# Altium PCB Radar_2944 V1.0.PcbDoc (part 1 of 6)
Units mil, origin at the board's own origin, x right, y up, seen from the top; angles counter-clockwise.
Board outline 3544.83 x 2556.65 mil, 8 copper layers (Top Layer, GND1, SIG1, PWR1, PWR2, SIG2, GND2, Bottom Layer), stack 55.2 mil thick; 301 components, 253 nets, 1055 pads, 1340 vias.
Unrouted connection lines stored in the file: 12.
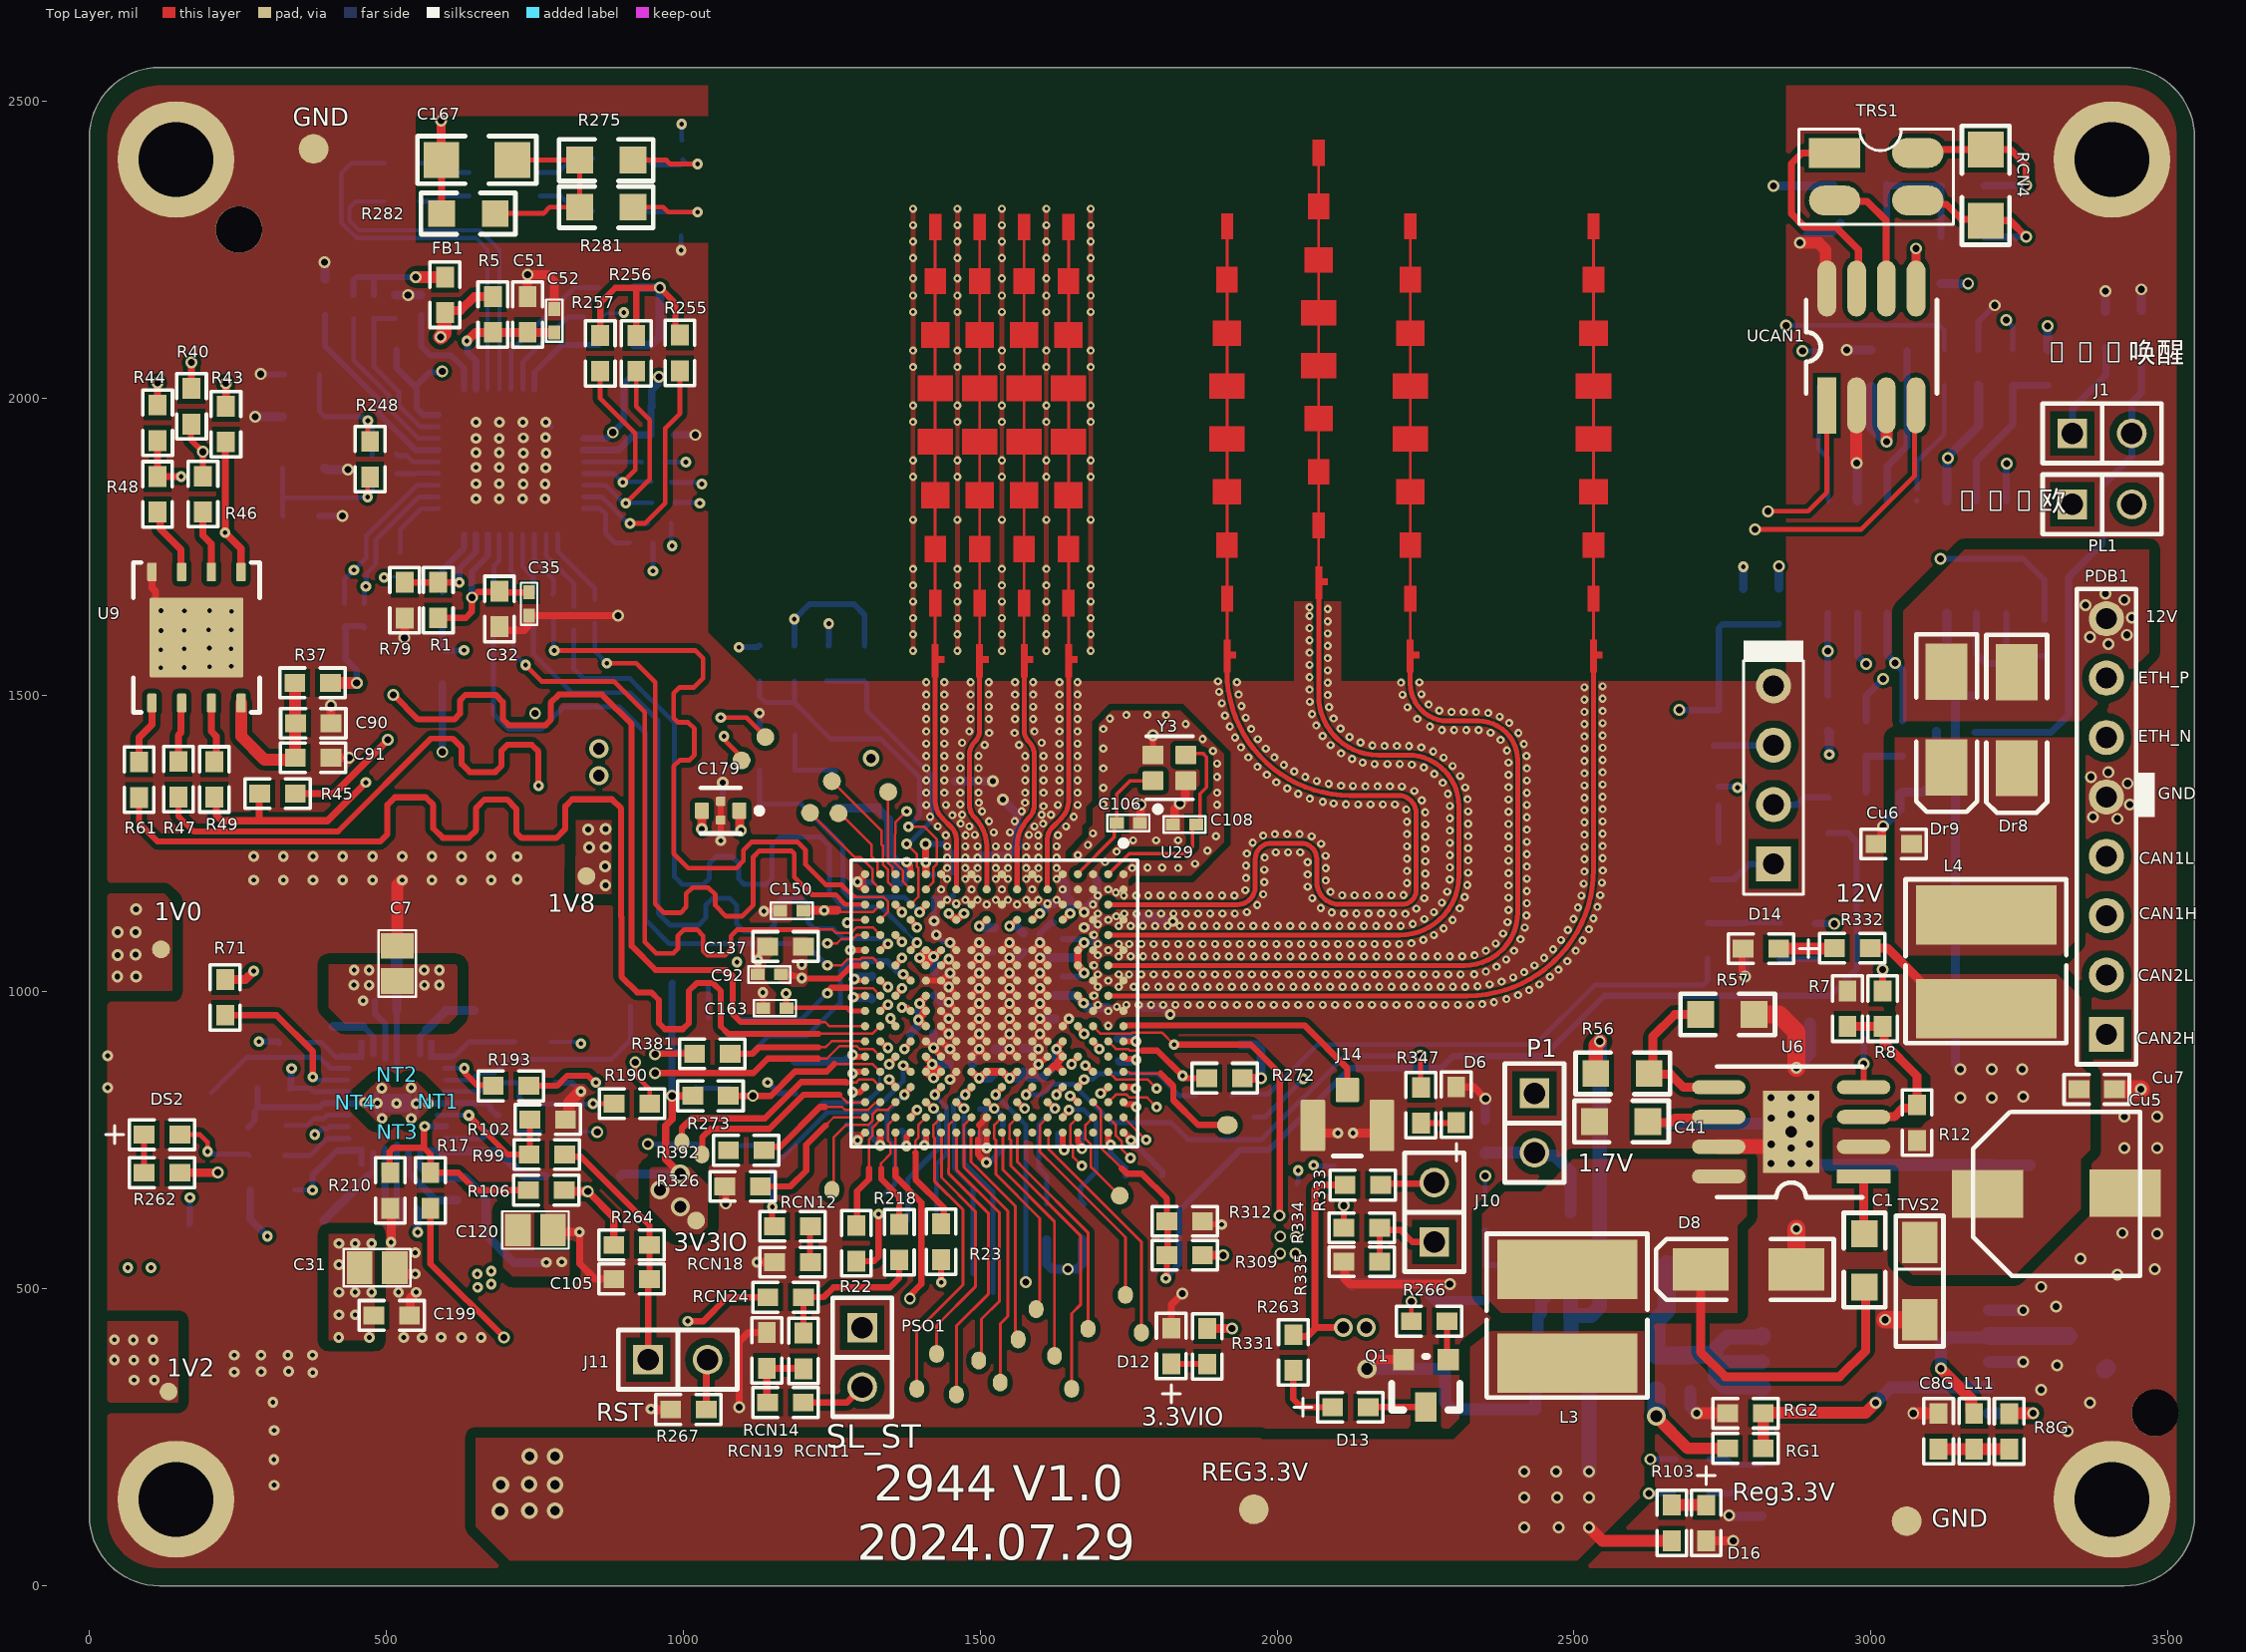
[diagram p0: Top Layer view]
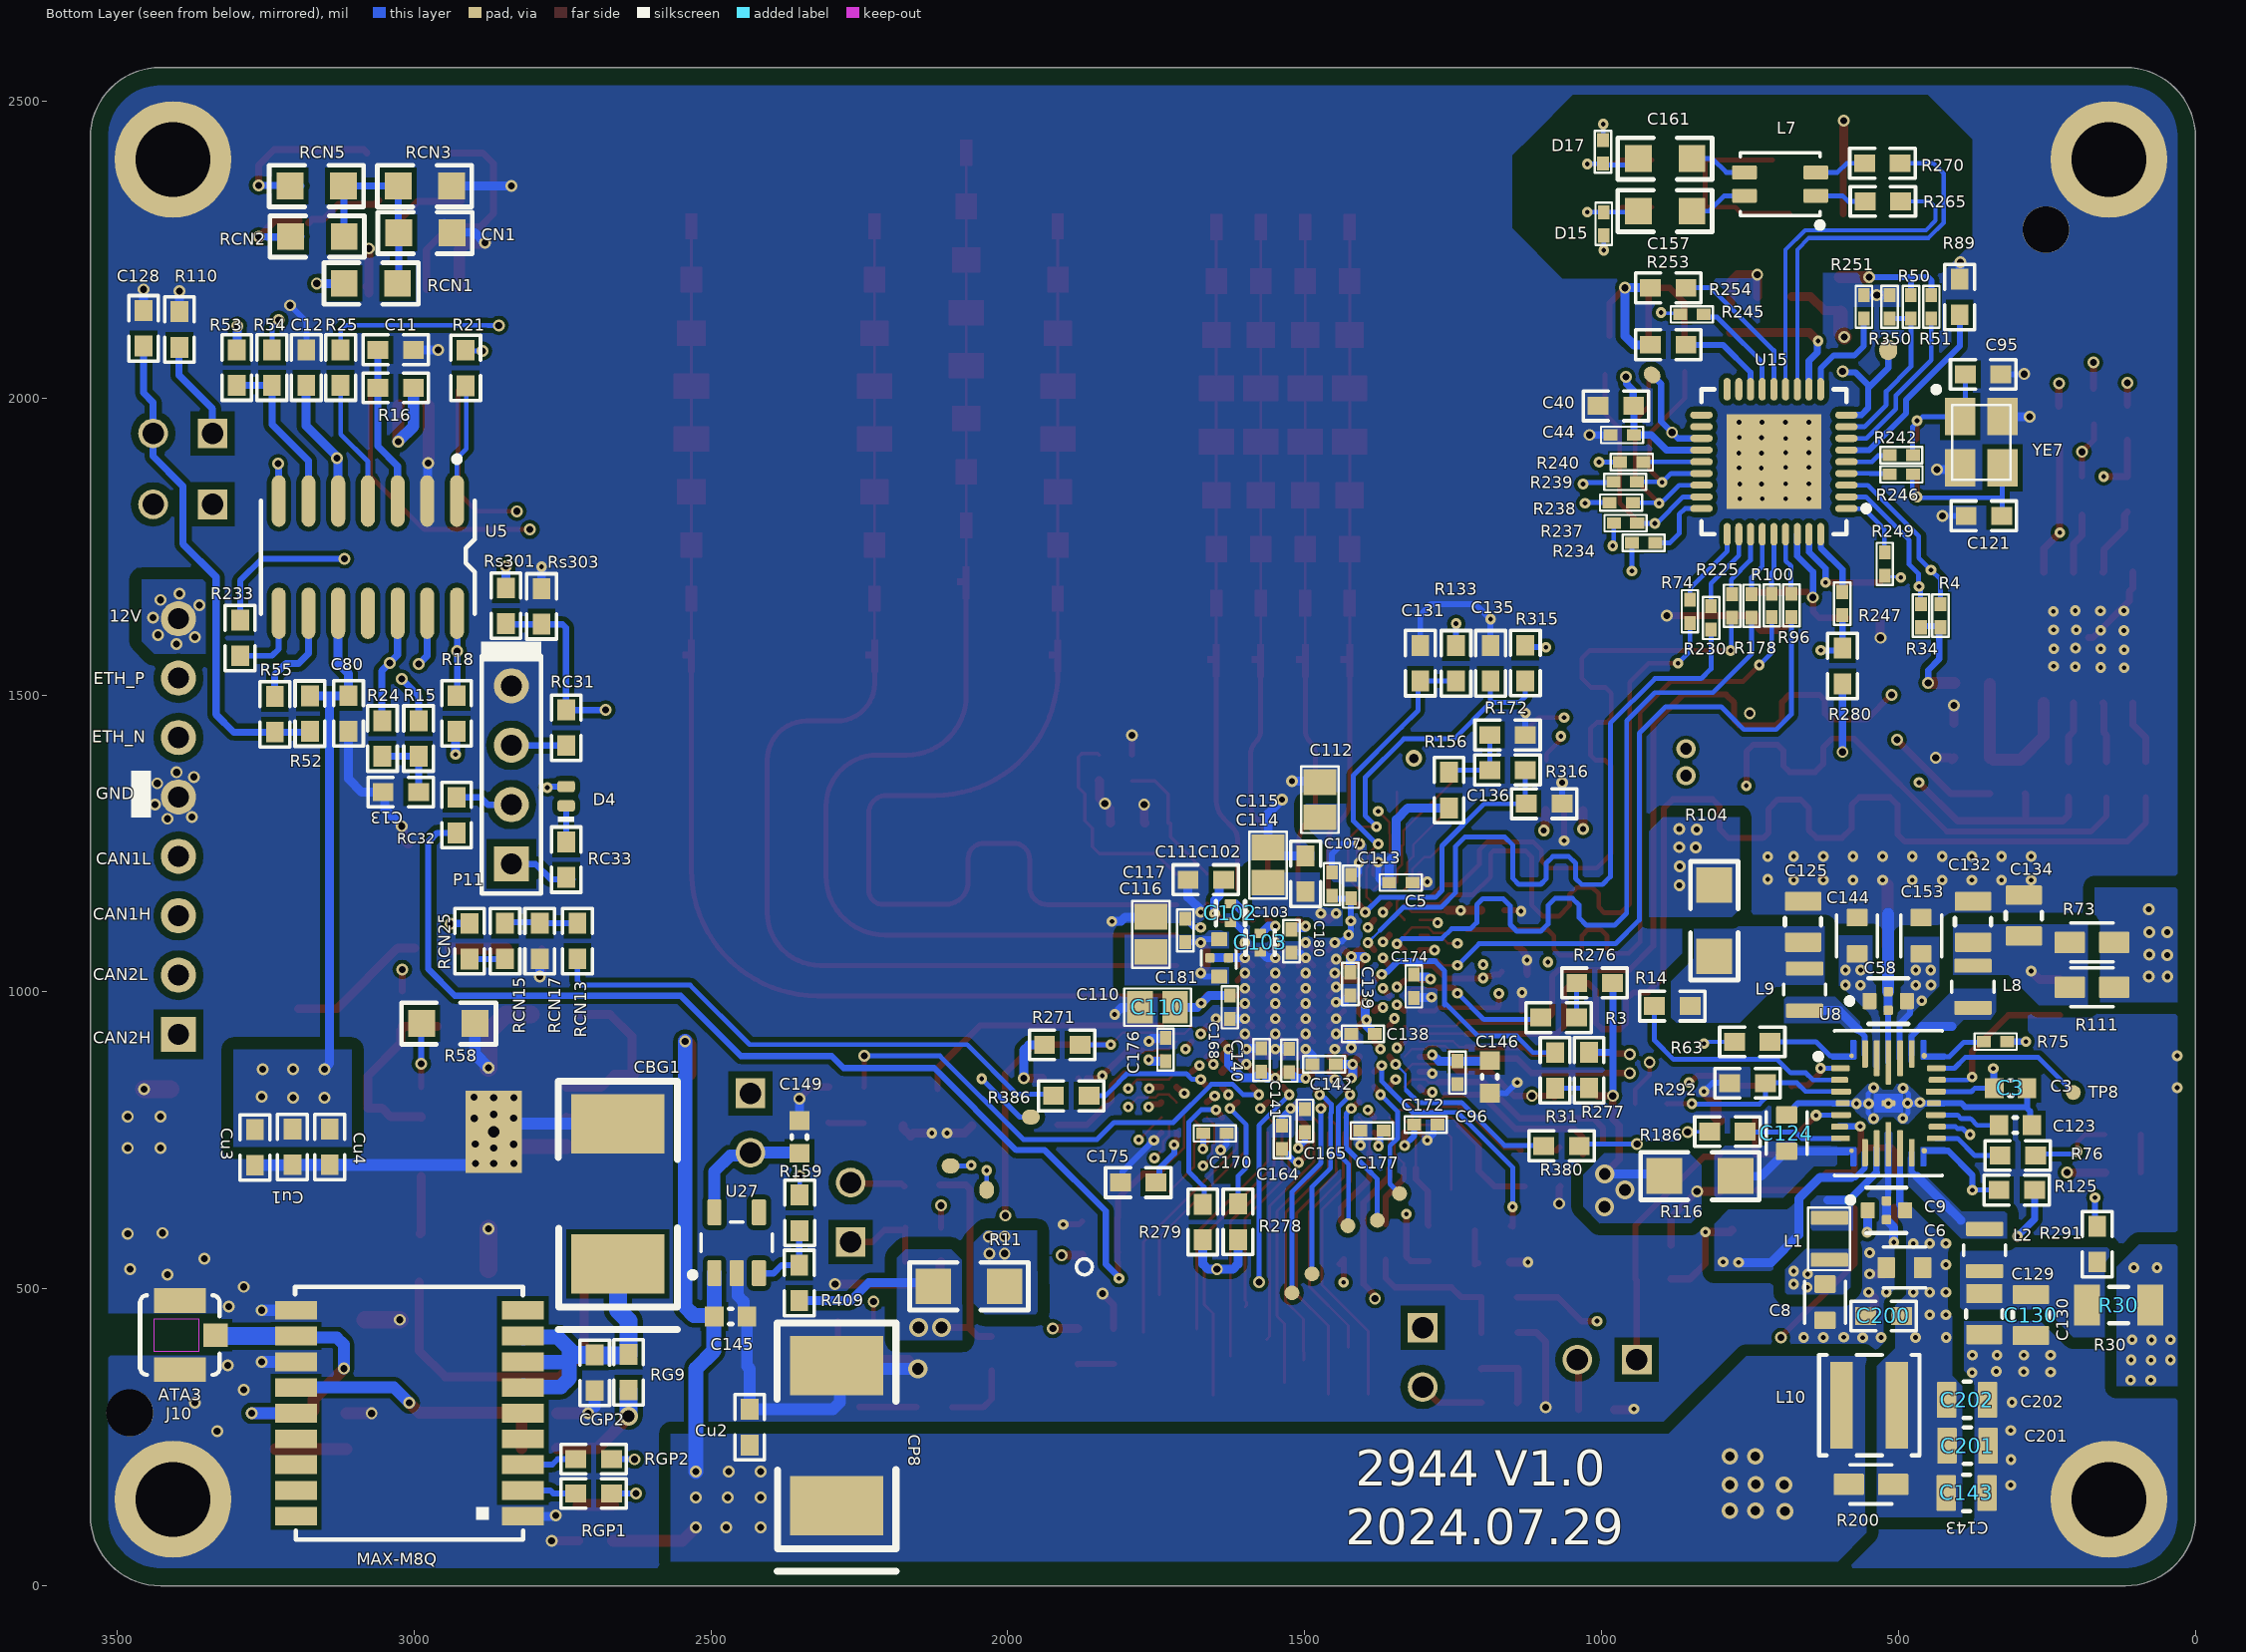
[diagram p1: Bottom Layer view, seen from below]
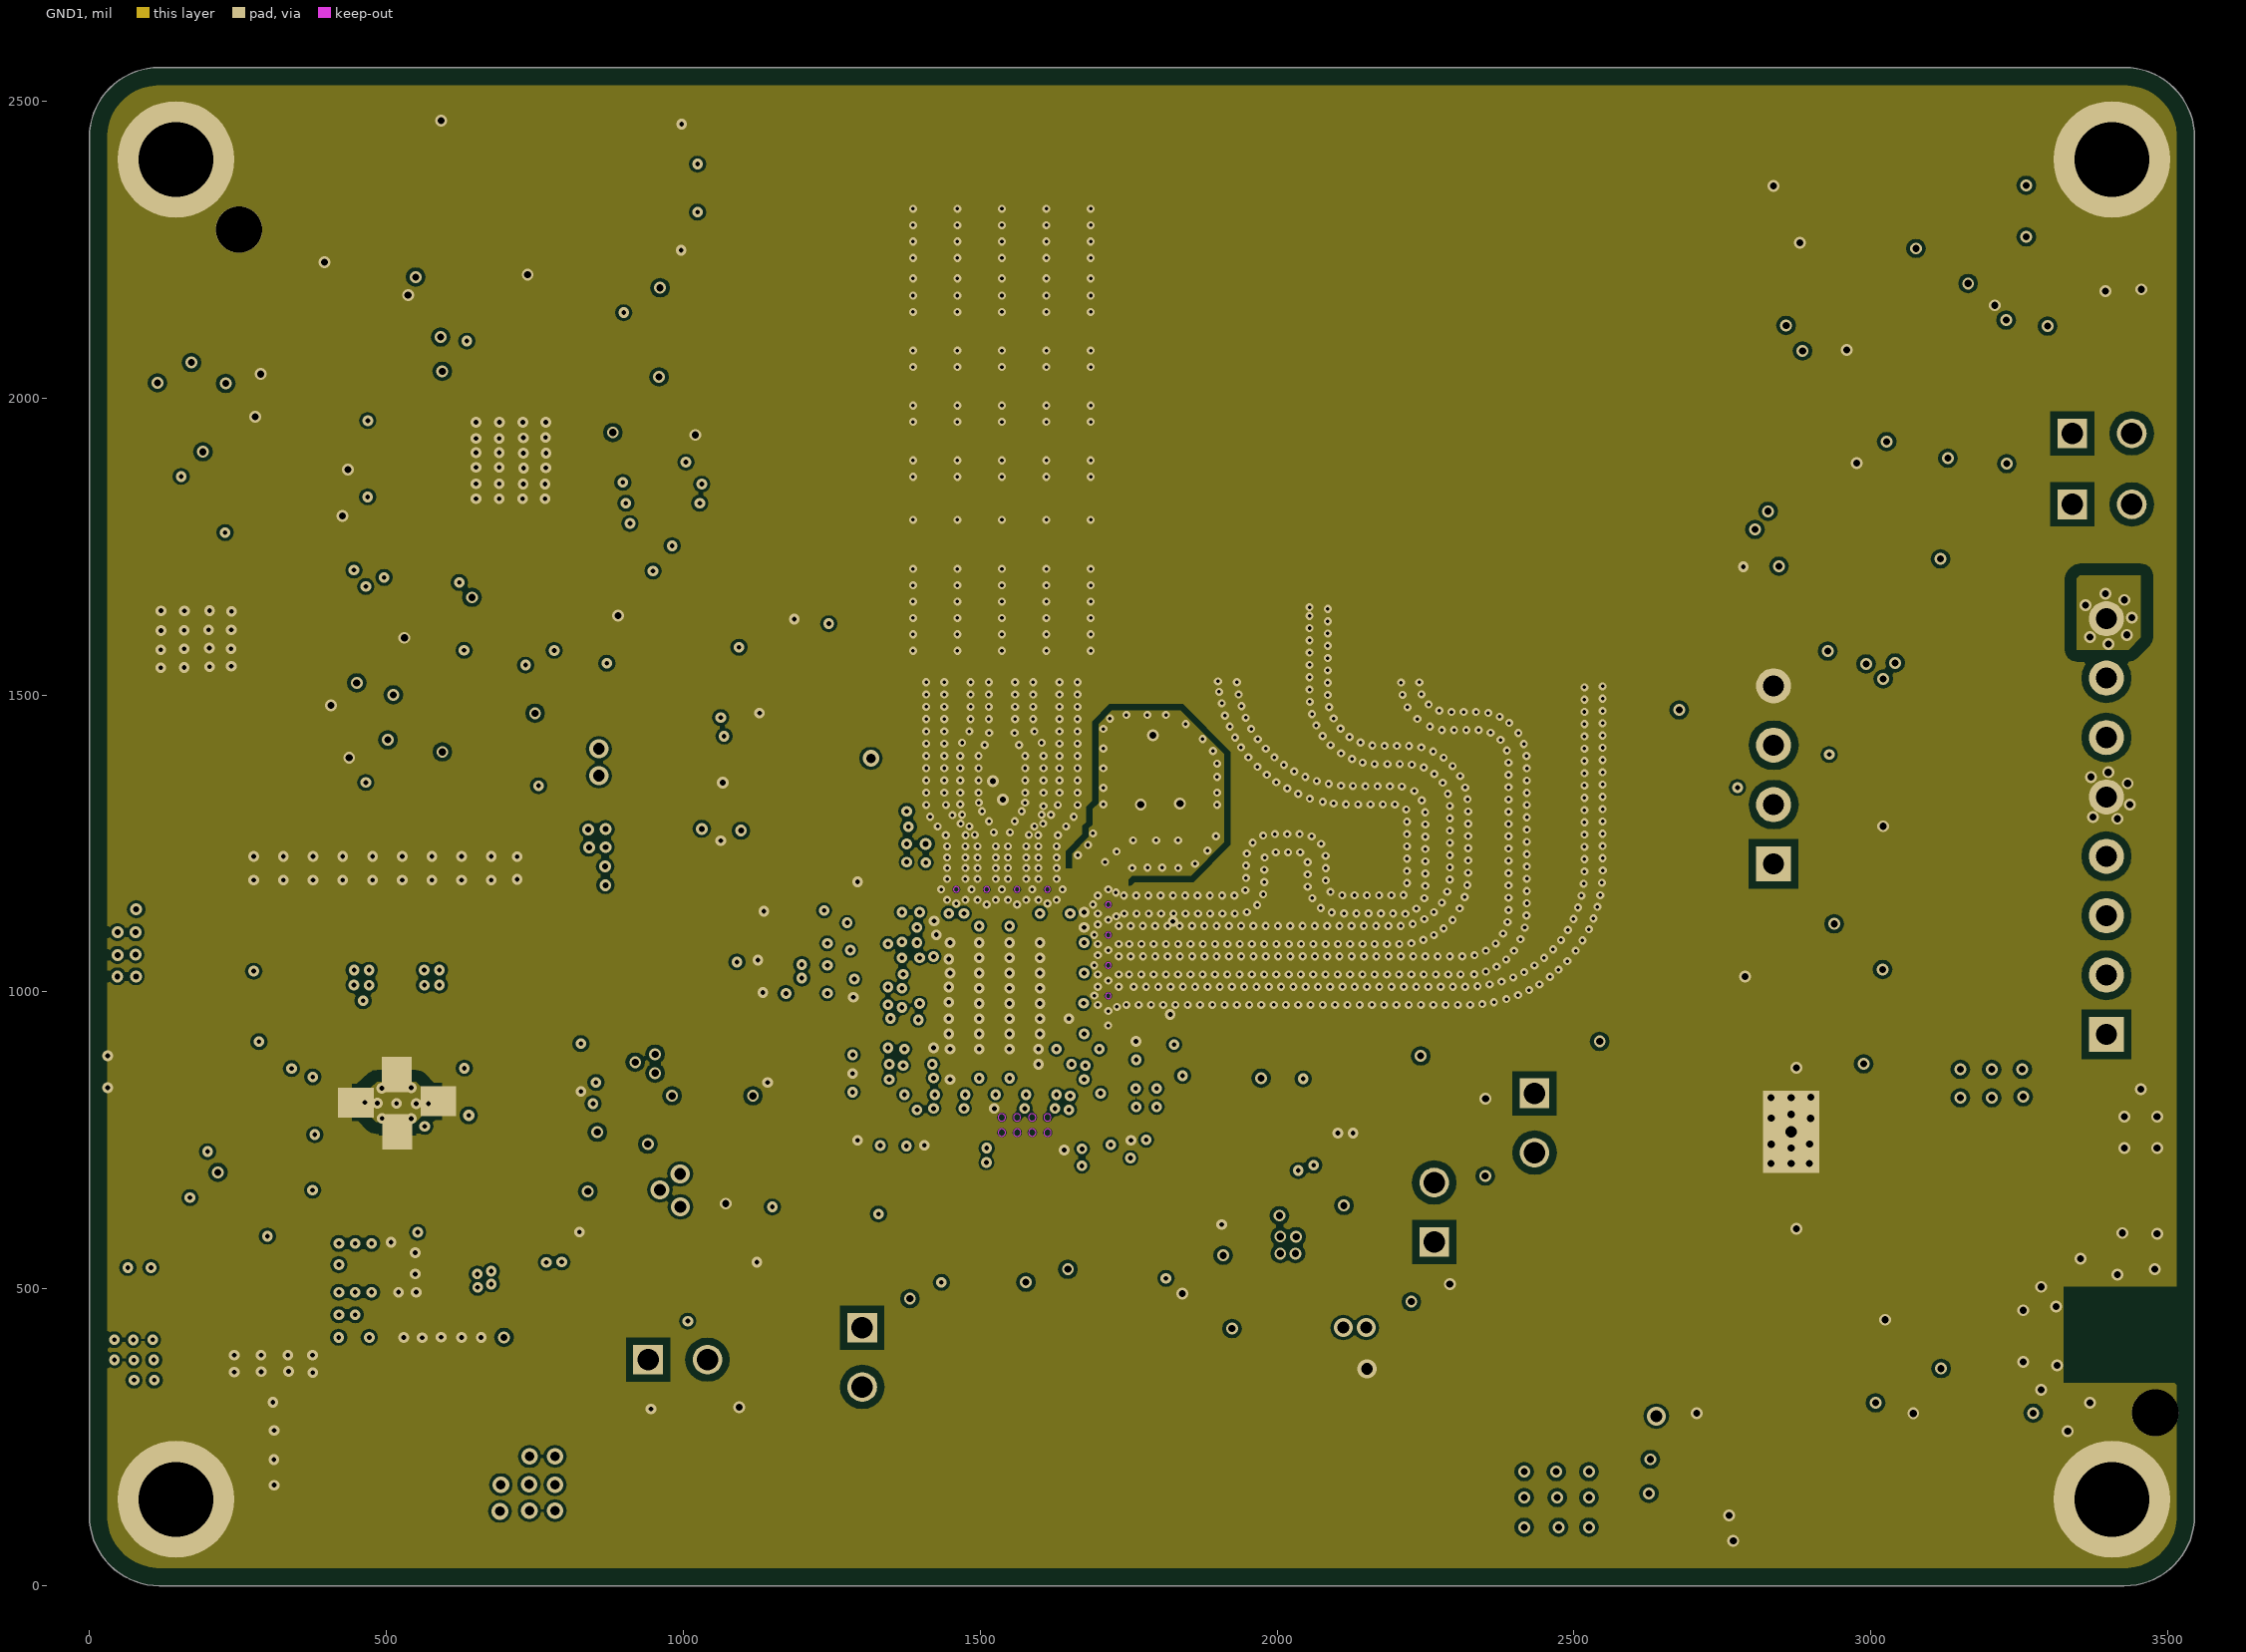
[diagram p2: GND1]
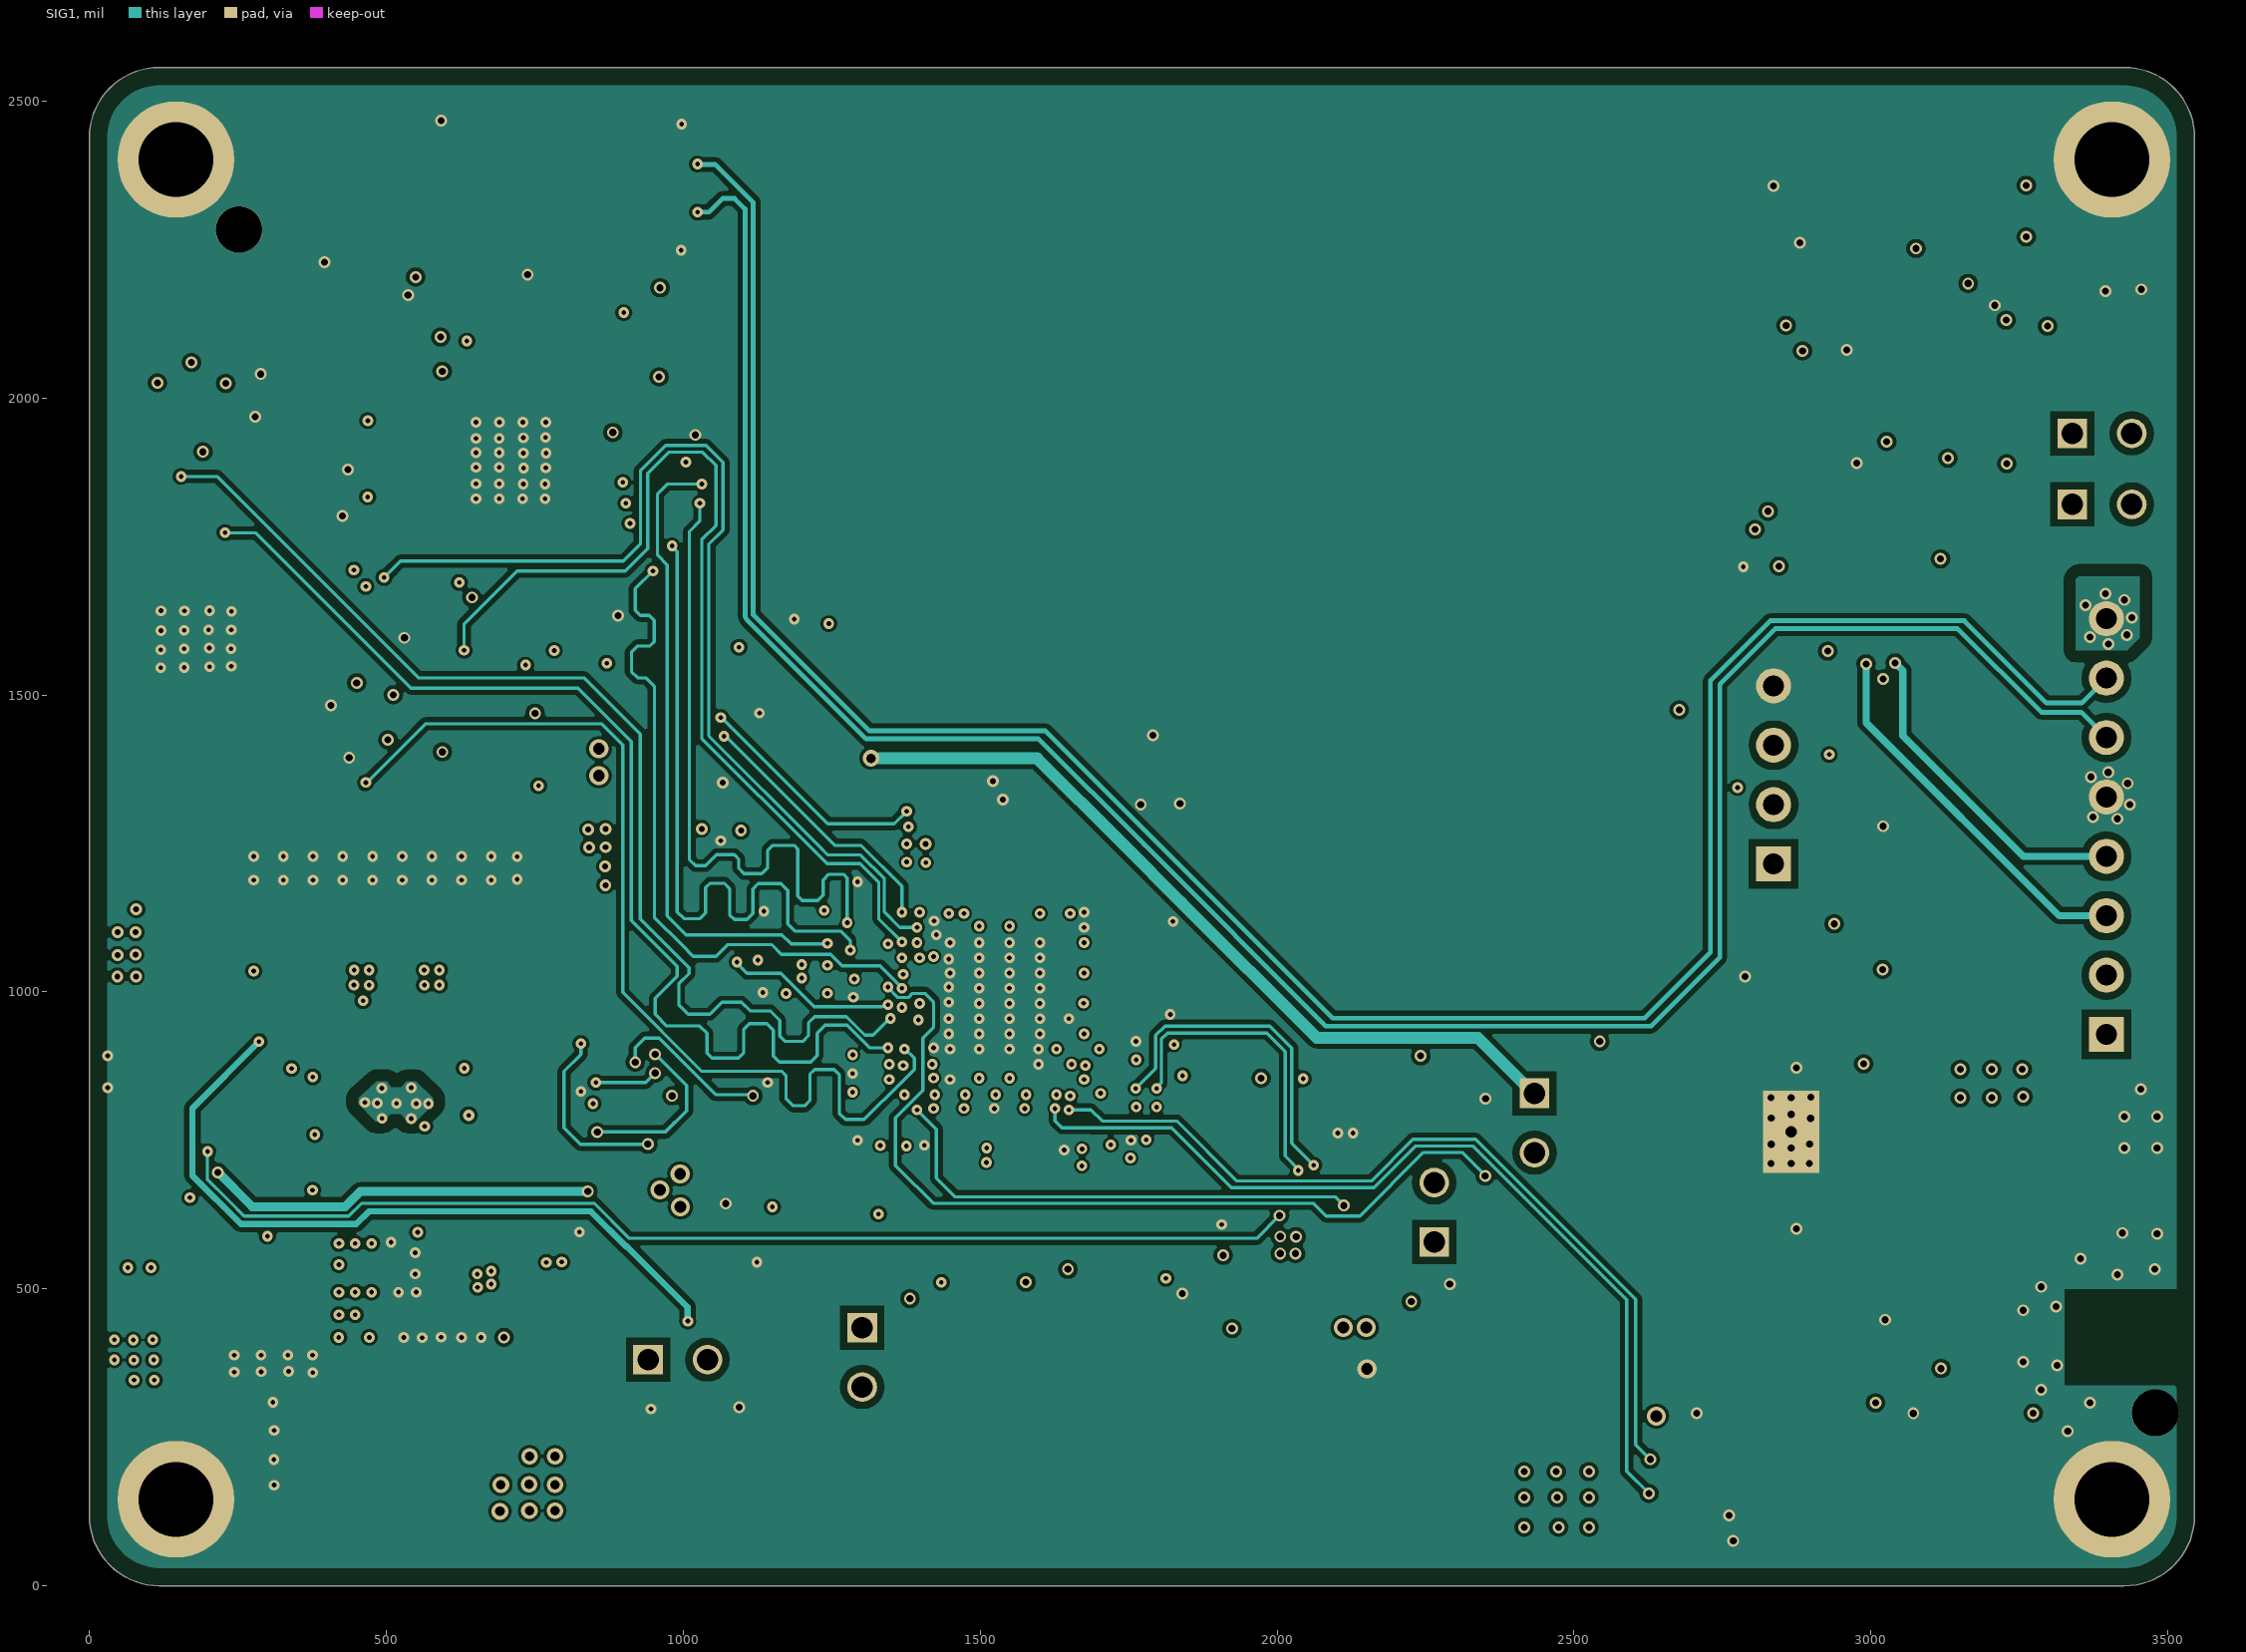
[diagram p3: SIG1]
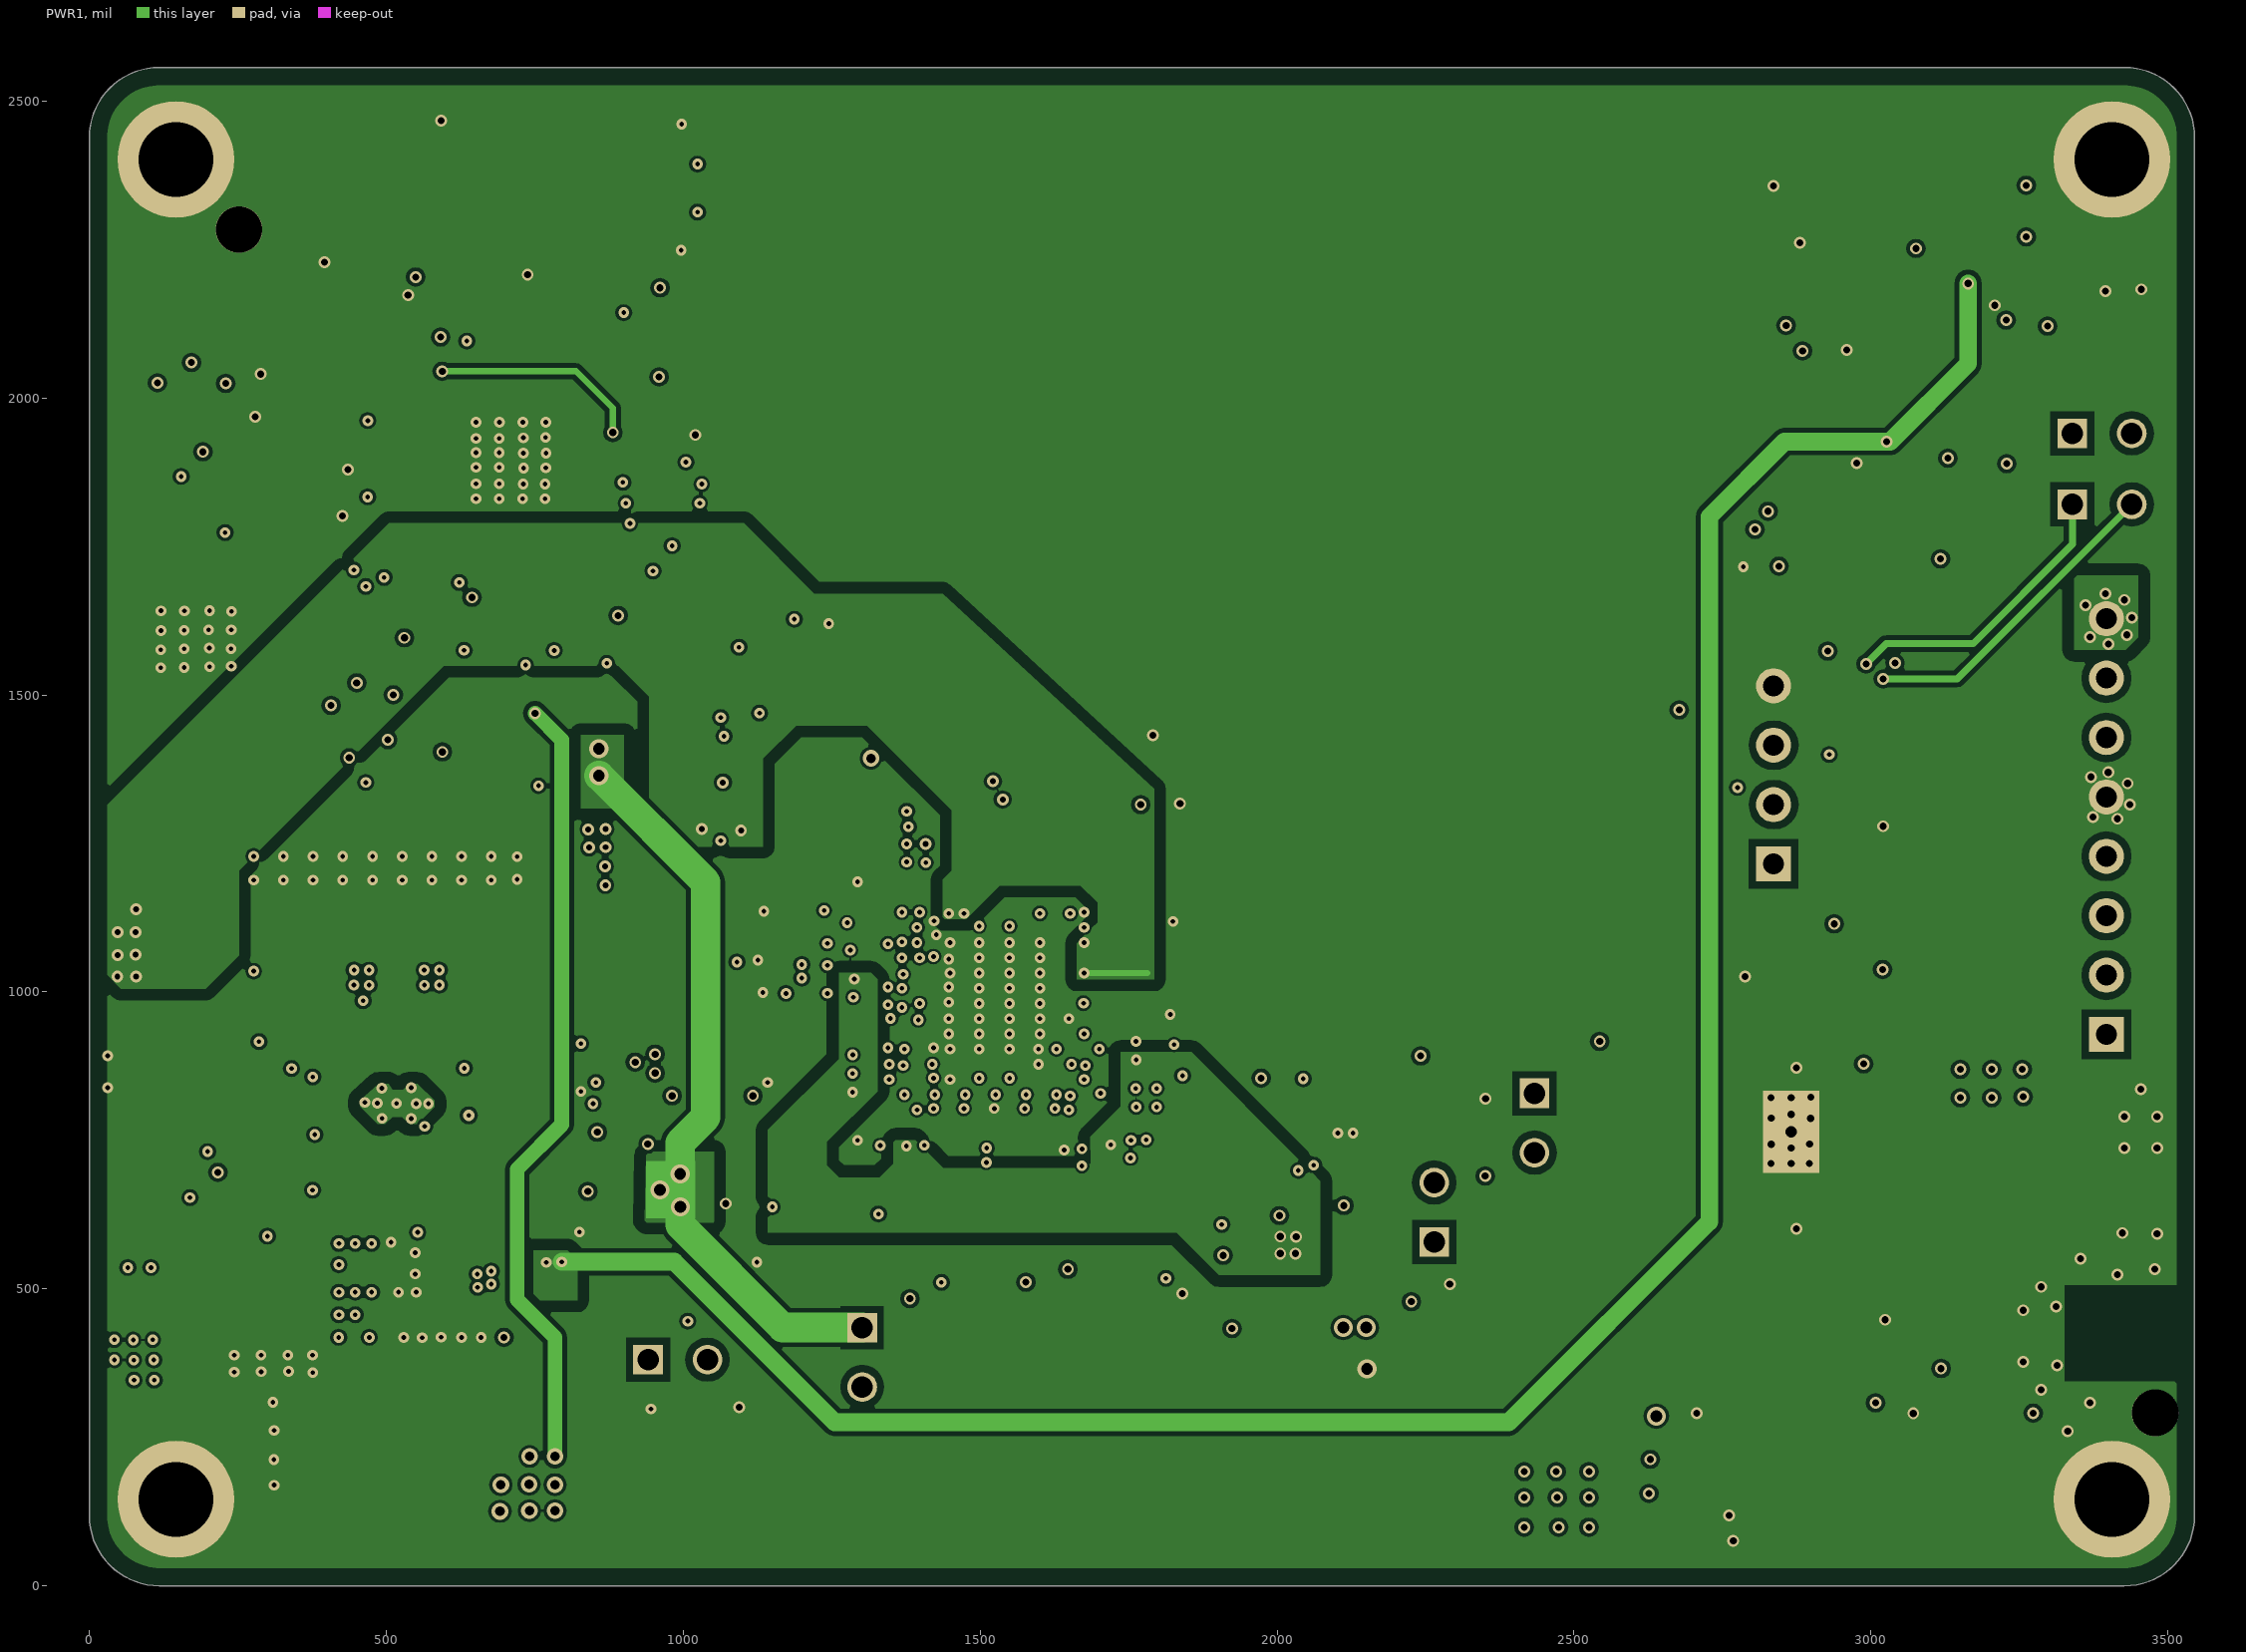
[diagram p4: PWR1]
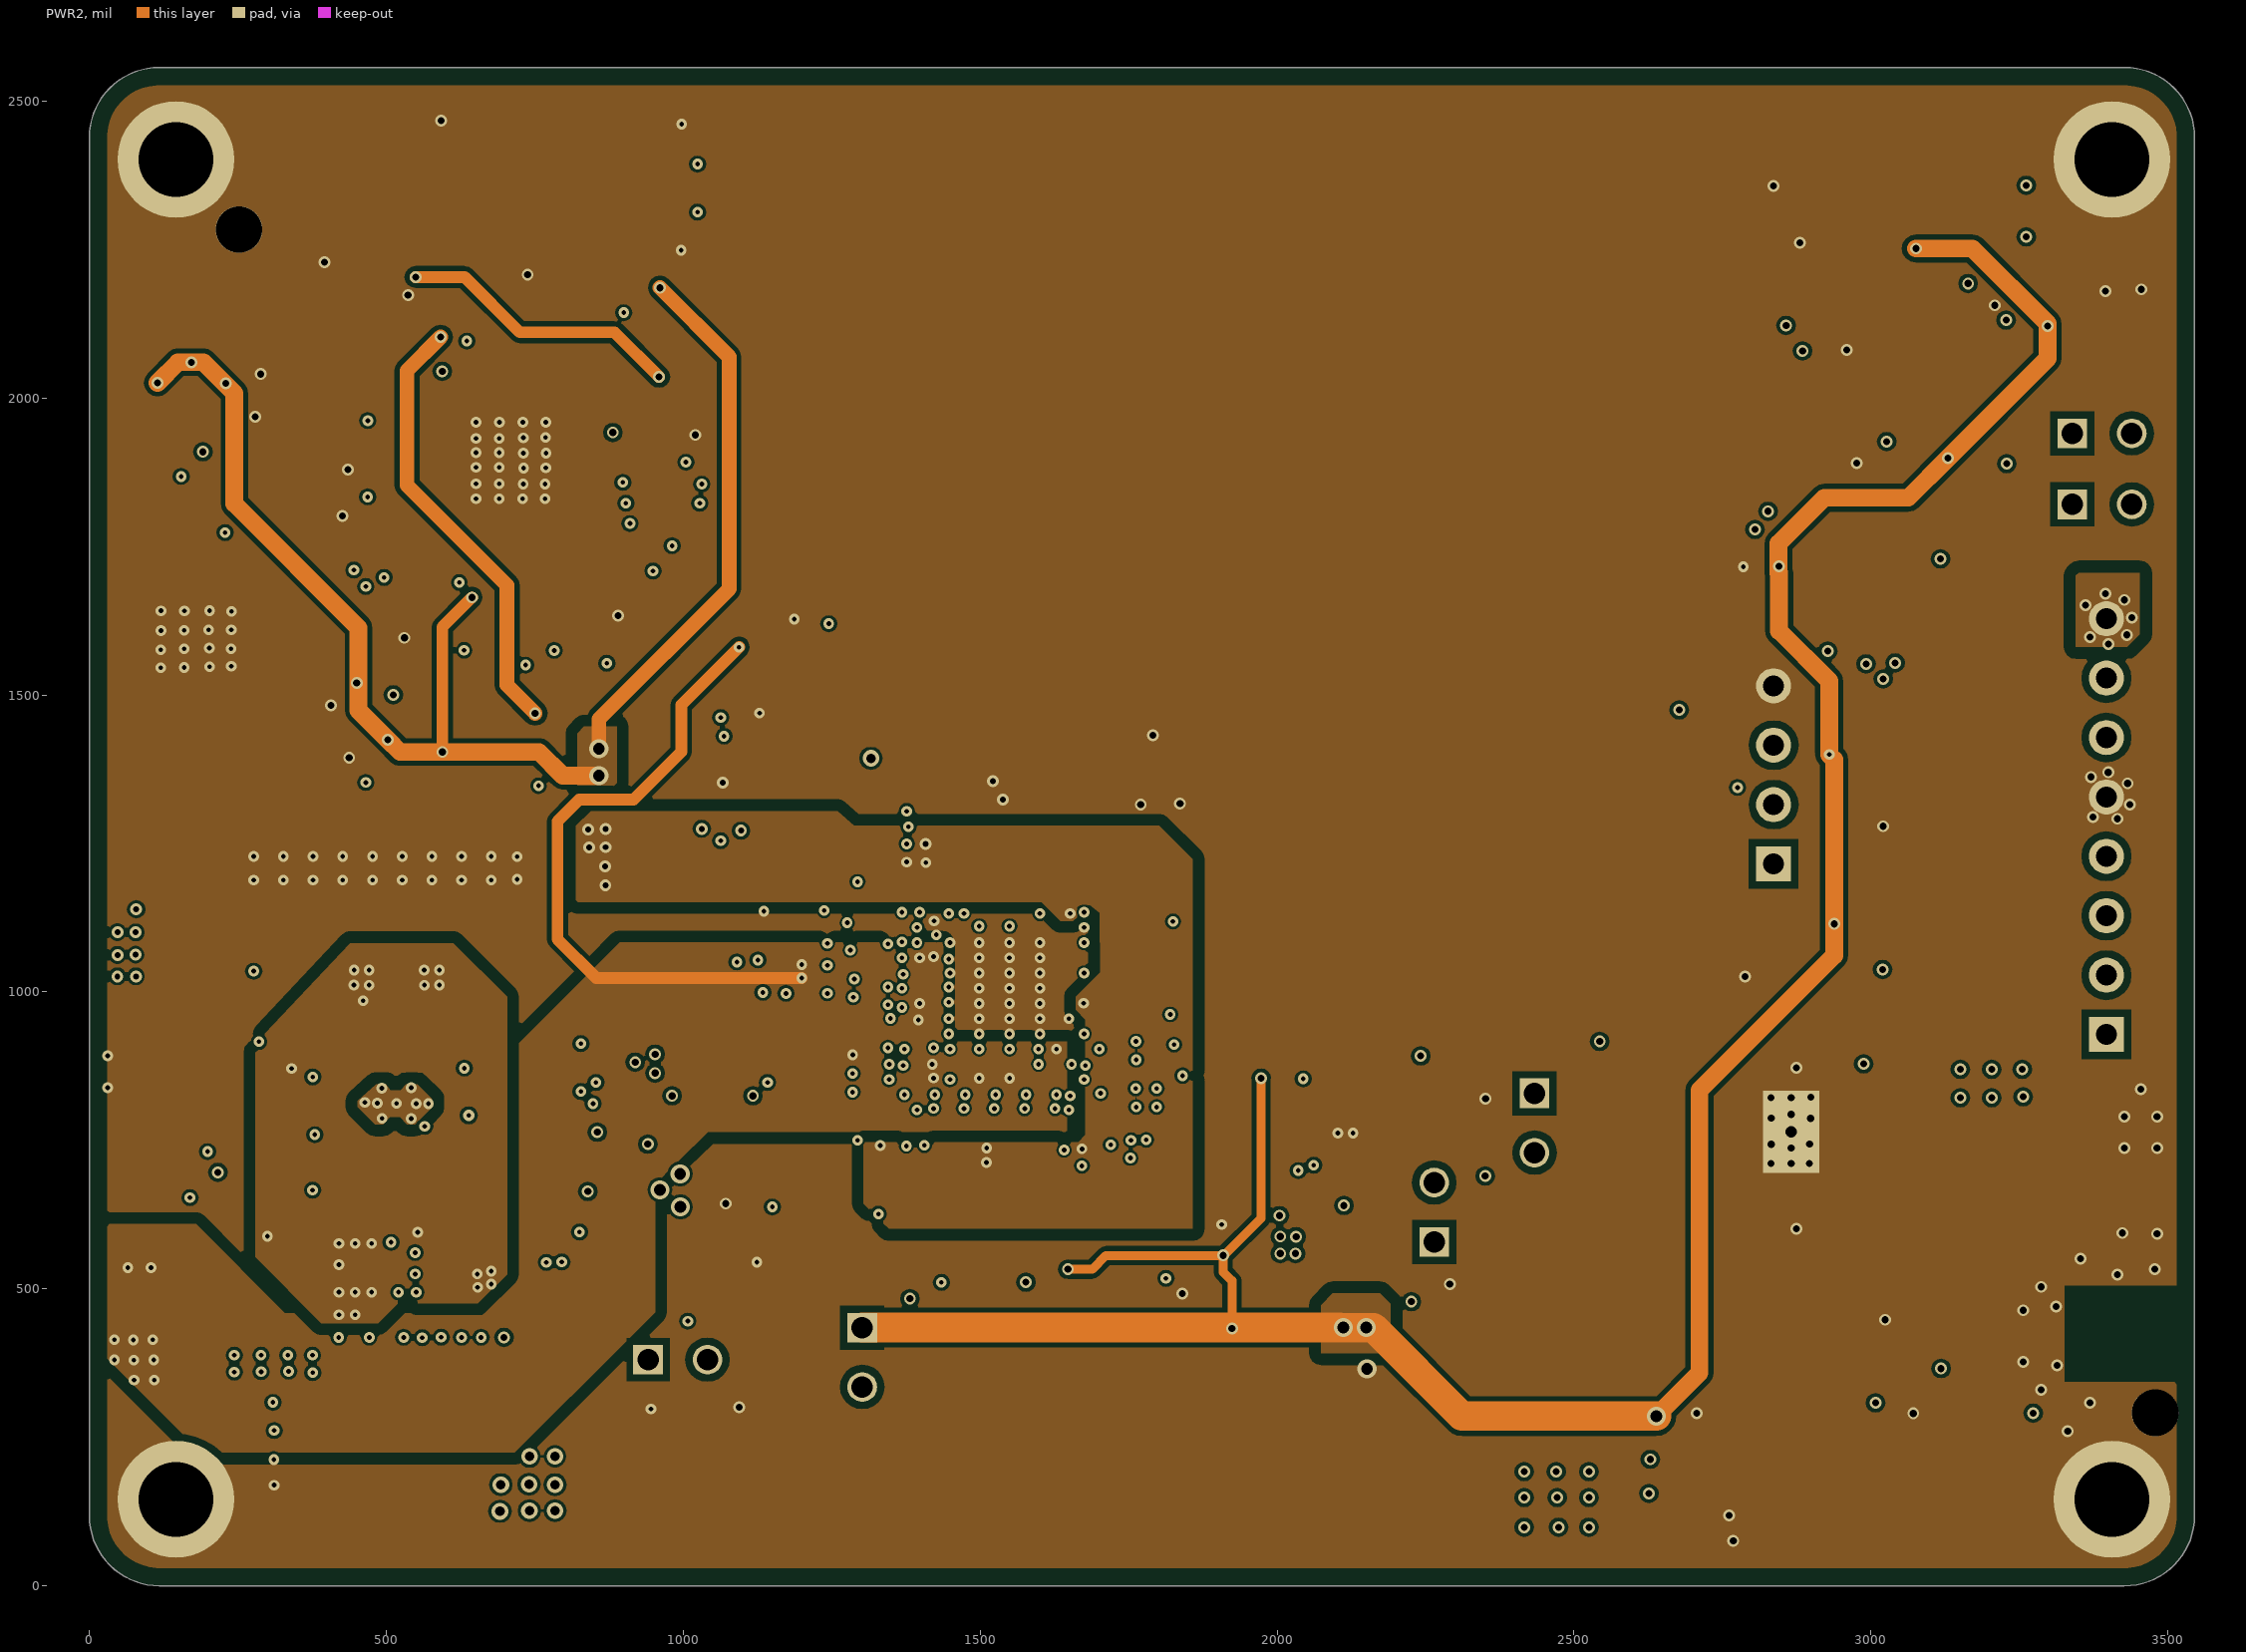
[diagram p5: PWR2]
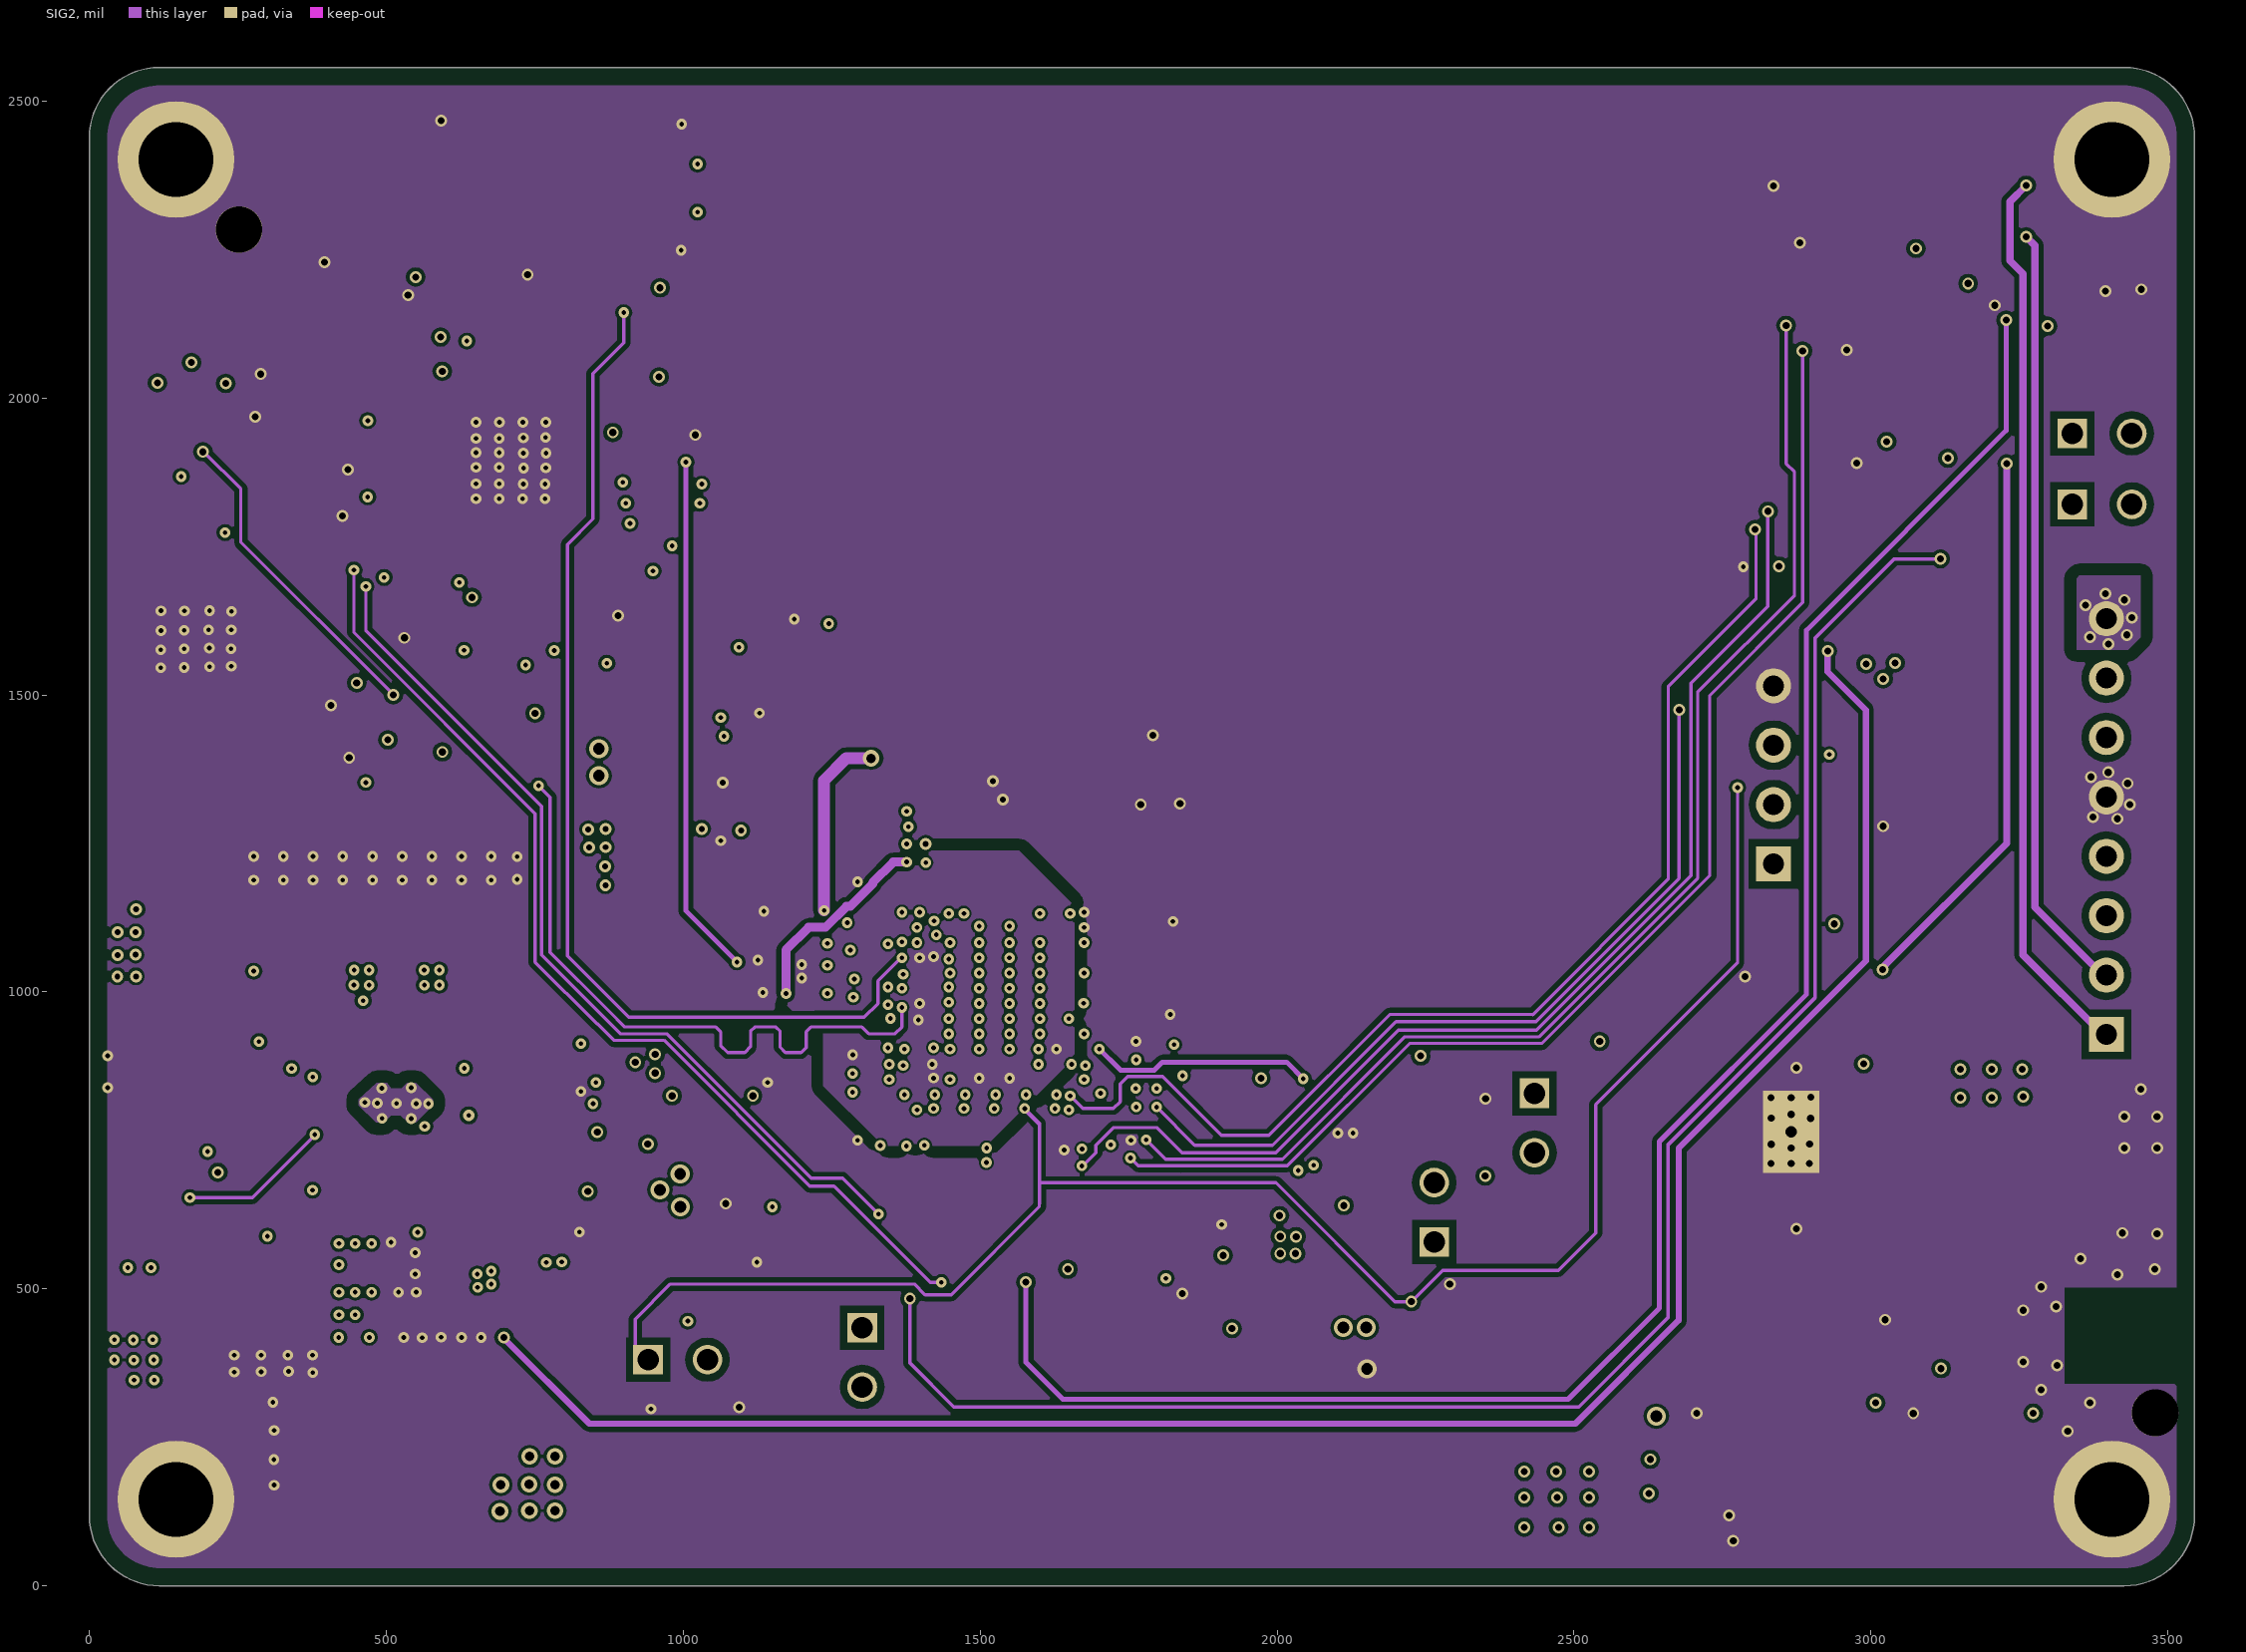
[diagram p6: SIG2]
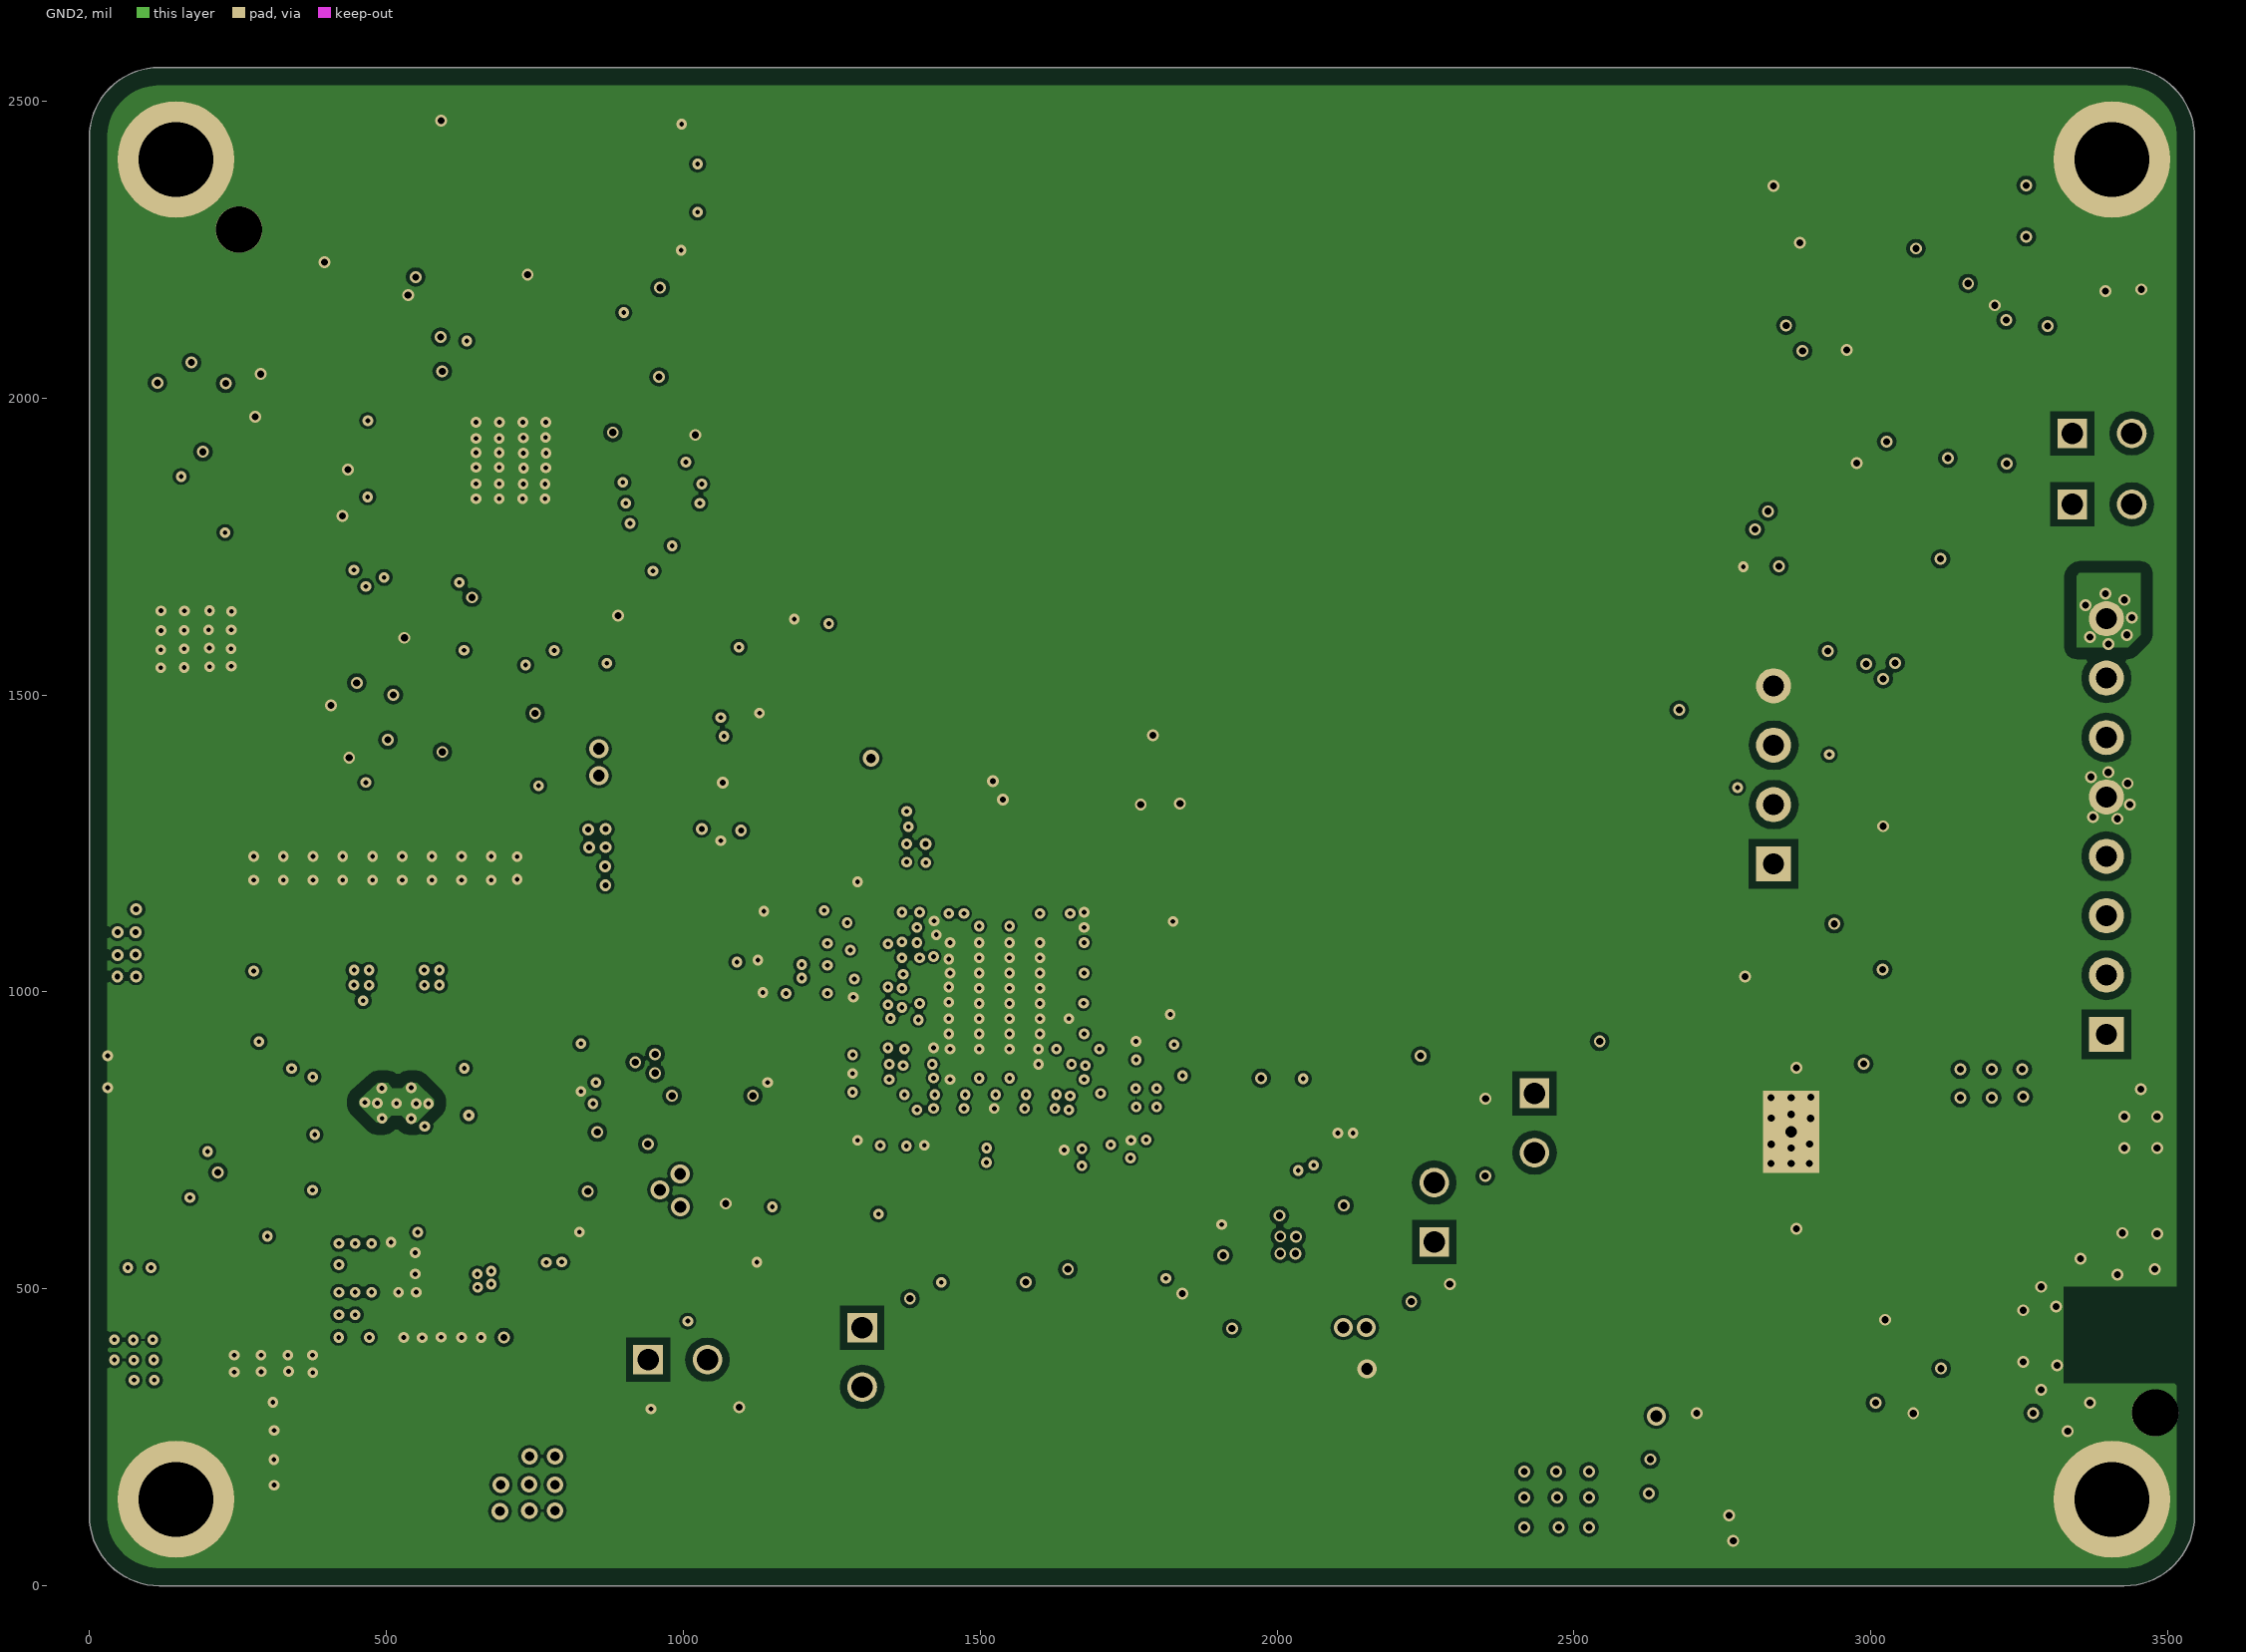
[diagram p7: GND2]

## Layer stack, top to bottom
Top Solder: solder mask 0.8, Solder Resist, Dk 3.5
Top Layer: signal copper 1.6
Dielectric 1: prepreg 5, RO3003, Dk 3
GND1: signal copper 1.4
Dielectric 2: core 5, FR-4 High Tg, Dk 4.04
SIG1: signal copper 0.7
Dielectric 3: prepreg 10, FR-4 High Tg, Dk 4.04
PWR1: signal copper 1.4
Dielectric 4: prepreg 5, FR-4 High Tg, Dk 4.04
PWR2: signal copper 1.4
Dielectric 5: prepreg 10, FR-4 High Tg, Dk 4.04
SIG2: signal copper 0.7
Dielectric 6: core 5, FR-4 High Tg, Dk 4.04
GND2: signal copper 1.4
Dielectric 7: prepreg 5, FR-4 High Tg, Dk 4.04
Bottom Layer: signal copper 1.6
Bottom Solder: solder mask 0.8, Solder Resist, Dk 3.5

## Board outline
0.01,118.17 0.01,2438.42 -0.02,2438.42 cw(c118.09,2438.42) 118.09,2556.53 3426.69,2556.53 cw(c3426.69,2438.42) 3544.81,2438.42 3544.78,2438.42 3544.78,117.99 3544.6,117.99 cw(c3426.49,117.99) 3426.49,-0.12 3426.49,0.01 118.17,0.01 118.17,0.06 cw(c118.17,118.17)

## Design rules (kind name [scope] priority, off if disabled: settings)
AcuteAngle [All] p1: minimum=4.50000000000000E+0001 checktracksonly=TRUE
AssemblyTestPointUsage [All] p1: valid=2
BoardOutlineClearance BoardOutlineClearance_MountingHoles [OnCopper and InComponentClass('Mounting Holes')] p1: gap=39.37 ignorepadtopadclearanceinfootprint=FALSE
BoardOutlineClearance BoardOutlineClearance_Poly [OnCopper and IsPoly] p2: gap=30 ignorepadtopadclearanceinfootprint=FALSE
BoardOutlineClearance [OnCopper and Not InComponentClass('Logo') and not InComponentClass('FiducialMark')and not InComponentClass('RA PARTS') and not InPoly] p3: gap=80 ignorepadtopadclearanceinfootprint=FALSE except(0: THPad-OutlineEdge Text-OutlineEdge Text-CavityEdge Text-CutoutEdge Text-SplitBarrior Text-SplitContinuation; 19: Fill-OutlineEdge; 30: Arc-OutlineEdge Track-OutlineEdge SMDPad-OutlineEdge Via-OutlineEdge Poly-OutlineEdge Region-OutlineEdge)
Clearance Clearance_2 [InComponent('PDB1')] p1: gap=8 ignorepadtopadclearanceinfootprint=TRUE except(0: SMDPad-Via THPad-Via Via-Via; 1: Arc-Text Track-Text SMDPad-Text THPad-Text Via-Text Fill-Text Poly-Text Region-Text Text-Text; 5.5: Arc-Arc Arc-Track Track-Track; 6: Via-Fill Via-Poly Via-Region; 7: Arc-Via Track-Via; 7.7: Arc-SMDPad Track-SMDPad; 9: Arc-Hole Track-Hole; 10: Via-Hole Fill-Hole Poly-Hole Region-Hole; 12: SMDPad-THPad SMDPad-Hole THPad-THPad THPad-Fill THPad-Poly THPad-Region THPad-Hole; 18: Fill-Fill Fill-Poly Fill-Region Poly-Poly Poly-Region Region-Region)
Clearance Clearance_1 [InNamedPolygon('Top Layer-AGND 1')] p2: gap=10 ignorepadtopadclearanceinfootprint=FALSE except(0: Arc-Hole Track-Hole SMDPad-Via SMDPad-Hole THPad-Hole Via-Hole Fill-Hole Poly-Hole Region-Hole Text-Hole)
Clearance Clearance_Keepouts [IsKeepOut] p3: gap=1 ignorepadtopadclearanceinfootprint=FALSE except(0: Arc-Via Track-Via SMDPad-Via)
Clearance RF_Via [InNetClass('Antenna')] p4: gap=10 ignorepadtopadclearanceinfootprint=TRUE except(0: Track-Region SMDPad-Via SMDPad-Region THPad-Region Via-Region; 3.78: Track-Poly; 3.94: Arc-Poly; 4: Arc-Via Arc-Hole Track-Via Track-Hole; 4.69: Poly-Region; 6: Region-Hole; 9.45: SMDPad-Poly)
Clearance Clearance_Poly_INT [InPolygon vs (OnLayer('GND1') OR OnLayer('SIG1') OR  OnLayer('GND2') OR OnLayer('PWR1') OR OnLayer('PWR2') OR OnLayer('GND3') OR OnLayer('SIG2') OR OnLayer('GND4'))] p5: gap=8 ignorepadtopadclearanceinfootprint=TRUE except(0: SMDPad-Via; 5: Arc-Text Track-Text SMDPad-Text THPad-Text Via-Text Fill-Text Poly-Text Region-Text Text-Text; 6: Arc-Via Track-Via SMDPad-Fill SMDPad-Poly SMDPad-Region; 10: Arc-THPad Arc-Hole Track-THPad Track-Hole Via-Fill Via-Poly Via-Region Via-Hole Fill-Hole Poly-Hole Region-Hole; 12: SMDPad-SMDPad SMDPad-THPad SMDPad-Hole THPad-THPad THPad-Hole Via-Via; 20: Fill-Fill Fill-Poly Fill-Region Poly-Poly Poly-Region Region-Region)
Clearance Clearance_FiducialMark [IsKeepOut and InComponentClass('FiducialMark') vs IsPad and InComponentClass('FiducialMark')] p6: gap=0 ignorepadtopadclearanceinfootprint=FALSE
Clearance 0.65MM_BGA [WithinRoom('BGA')] p7: gap=1 ignorepadtopadclearanceinfootprint=TRUE except(0: Arc-Region Track-Region SMDPad-Via SMDPad-Region THPad-Region Via-Region; 3.81: Arc-SMDPad Track-SMDPad; 3.9: Arc-Arc Arc-Track Track-Track; 4: Arc-Via Arc-Fill Arc-Poly Track-Via Track-Fill Via-Fill Via-Poly; 5: Via-Via; 7: Via-Hole; 8: Arc-Hole Track-Poly Track-Hole SMDPad-SMDPad SMDPad-Fill SMDPad-Poly SMDPad-Hole Fill-Hole Text-Hole; 12: Arc-THPad Track-THPad SMDPad-THPad THPad-THPad THPad-Via THPad-Fill THPad-Poly THPad-Hole; 20: Fill-Fill Fill-Poly Fill-Region Poly-Poly Poly-Region Region-Region)
Clearance DIFF_100E_EXT_Same [InDifferentialPairClass('DIFF_100E') vs (OnLayer('Top Layer') OR OnLayer('Bottom Layer'))] p8: gap=12 ignorepadtopadclearanceinfootprint=TRUE except(0: Track-Via Track-Region SMDPad-Via SMDPad-Region Via-Region; 1: Arc-Text Track-Text SMDPad-Text THPad-Text Via-Text Fill-Text Poly-Text Region-Text Text-Text; 3.9: Track-Track; 4.19: Arc-Via Track-SMDPad; 6: Via-Fill Via-Poly; 7: Arc-Arc Arc-Track; 8: Arc-SMDPad Arc-Fill Arc-Poly Arc-Region Track-Fill Track-Poly SMDPad-SMDPad Text-Hole; 9.5: Arc-Hole Track-Hole; 10: SMDPad-Fill SMDPad-Poly Via-Via Via-Hole Fill-Poly Fill-Hole Poly-Hole Region-Hole; 25: Fill-Fill Fill-Region Poly-Poly Poly-Region Region-Region)
Clearance DIFF_100E_EXT [InDifferentialPairClass('DIFF_100E') vs (OnLayer('Top Layer') OR OnLayer('Bottom Layer'))] p9: gap=12 ignorepadtopadclearanceinfootprint=TRUE except(0: Track-Via Track-Region SMDPad-Via SMDPad-Region Via-Region; 1: Arc-Text Track-Text SMDPad-Text THPad-Text Via-Text Fill-Text Poly-Text Region-Text Text-Text; 4.19: Arc-Via Track-SMDPad; 6: Via-Fill Via-Poly; 7: Arc-Arc Arc-Track; 8: Arc-SMDPad Arc-Fill Arc-Poly Arc-Region Track-Fill Track-Poly SMDPad-SMDPad Text-Hole; 9.5: Arc-Hole Track-Hole; 10: Track-Track SMDPad-Fill SMDPad-Poly Via-Via Via-Hole Fill-Poly Fill-Hole Poly-Hole Region-Hole; 25: Fill-Fill Fill-Region Poly-Poly Poly-Region Region-Region)
Clearance DIFF_90E_EXT_Same [InDifferentialPairClass('DIFF_90E') vs (OnLayer('Top Layer') OR OnLayer('Bottom Layer'))] p10: gap=12 ignorepadtopadclearanceinfootprint=TRUE except(0: SMDPad-Via; 1: Arc-Text Track-Text SMDPad-Text THPad-Text Via-Text Fill-Text Poly-Text Region-Text Text-Text; 4: Track-Track; 4.19: Arc-Via Track-SMDPad; 5: Track-Via; 6: Via-Fill Via-Poly Via-Region; 7: Arc-Arc Arc-Track; 8: Arc-SMDPad Arc-Fill Arc-Poly Arc-Region Track-Fill Track-Poly Track-Region SMDPad-SMDPad Text-Hole; 9.5: Arc-Hole Track-Hole; 10: SMDPad-Fill SMDPad-Poly SMDPad-Region Via-Via Via-Hole Fill-Poly Fill-Hole Poly-Hole Region-Hole; 25: Fill-Fill Fill-Region Poly-Poly Poly-Region Region-Region)
Clearance DIFF_90E_EXT [InDifferentialPairClass('DIFF_90E') vs (OnLayer('Top Layer') OR OnLayer('Bottom Layer'))] p11: gap=1 ignorepadtopadclearanceinfootprint=TRUE except(0: SMDPad-Via SMDPad-Region THPad-Region Via-Region; 4.19: Arc-Via Track-SMDPad; 5: Track-Via; 6: Via-Fill Via-Poly; 7: Arc-Arc Arc-Track; 8: Arc-SMDPad Arc-Fill Arc-Poly Arc-Region Track-Fill Track-Poly Track-Region SMDPad-SMDPad Text-Hole; 9.5: Arc-Hole Track-Hole; 10: SMDPad-Fill SMDPad-Poly Via-Via Via-Hole Fill-Poly Fill-Hole Poly-Hole Region-Hole; 12: Arc-THPad Track-THPad SMDPad-THPad SMDPad-Hole THPad-THPad THPad-Via THPad-Fill THPad-Poly THPad-Hole; 13.4: Track-Track; 25: Fill-Fill Fill-Region Poly-Poly Poly-Region Region-Region)
Clearance DIFF_120E_EXT [InDifferentialPairClass('DIFF_120E') vs (OnLayer('Top Layer') OR OnLayer('Bottom Layer'))] p12: gap=1 ignorepadtopadclearanceinfootprint=TRUE except(0: SMDPad-Via SMDPad-Region THPad-Region Via-Region; 4.5: Arc-Track Track-Track; 5: Arc-Via Track-Via; 5.6: Arc-Arc; 6: Via-Fill Via-Poly; 7: Arc-SMDPad Track-SMDPad; 8: Arc-Fill Arc-Region Track-Fill Track-Region SMDPad-SMDPad Text-Hole; 9.5: Arc-Hole Track-Hole; 10: SMDPad-Fill SMDPad-Poly Via-Via Via-Hole Fill-Poly Fill-Hole Poly-Hole Region-Hole; 12: Arc-THPad Track-THPad SMDPad-THPad SMDPad-Hole THPad-THPad THPad-Via THPad-Fill THPad-Poly THPad-Hole; 20: Arc-Poly Track-Poly; 25: Fill-Fill Fill-Region Poly-Poly Poly-Region Region-Region)
Clearance Clearance_TOP [All and (not InAnyDifferentialPair) vs OnLayer('Top Layer')] p13: gap=8 ignorepadtopadclearanceinfootprint=TRUE except(0: SMDPad-Via; 1: Arc-Text Track-Text SMDPad-Text THPad-Text Via-Text Fill-Text Poly-Text Region-Text Text-Text; 5: Arc-Via Track-Via; 6: Via-Fill Via-Poly Via-Region; 7: Arc-Arc Arc-Track Arc-SMDPad Track-Track Track-SMDPad; 9: Arc-Hole Track-Hole; 10: Via-Via Via-Hole Fill-Hole Poly-Hole Region-Hole; 12: SMDPad-THPad SMDPad-Hole THPad-THPad THPad-Via THPad-Fill THPad-Poly THPad-Region THPad-Hole; 18: Fill-Fill Fill-Poly Fill-Region Poly-Poly Poly-Region Region-Region)
Clearance Clearance_SOLD [All and (not InAnyDifferentialPair) vs OnLayer('Bottom Layer')] p14: gap=8 ignorepadtopadclearanceinfootprint=TRUE except(0: SMDPad-Region THPad-Region Via-Region; 1: Arc-Text Track-Region Track-Text SMDPad-Text THPad-Text Via-Text Fill-Text Poly-Text Region-Text Text-Text; 5: Arc-Via Track-Via; 6: Via-Fill Via-Poly; 7: Arc-Arc Arc-Track Arc-SMDPad Track-SMDPad; 8.3: Track-Track; 9: Arc-Hole Track-Hole; 10: Via-Via Via-Hole Fill-Hole Poly-Hole Region-Hole; 12: SMDPad-THPad SMDPad-Hole THPad-THPad THPad-Via THPad-Fill THPad-Poly THPad-Hole; 15: Poly-Region; 16: Fill-Region Region-Region; 18: Fill-Fill Fill-Poly; 20: Poly-Poly)
Clearance DIFF_100E_INT_Same [InDifferentialPairClass('DIFF_100E') vs (OnLayer('SIG1') OR OnLayer('SIG2'))] p15: gap=8 ignorepadtopadclearanceinfootprint=TRUE except(1: Arc-Text Track-Text SMDPad-Text THPad-Text Via-Text Fill-Text Poly-Text Region-Text Text-Text; 5: Arc-Via Track-Via; 6: Via-Fill Via-Poly Via-Region; 7.3: Arc-Arc Arc-Track Track-Track; 9.5: Arc-Hole Track-Hole; 10: SMDPad-Via SMDPad-Fill SMDPad-Poly SMDPad-Region Via-Via Via-Hole Fill-Hole Poly-Hole Region-Hole; 12: Arc-THPad Track-THPad SMDPad-THPad SMDPad-Hole THPad-THPad THPad-Via THPad-Fill THPad-Poly THPad-Region THPad-Hole; 25: Fill-Fill Fill-Poly Fill-Region Poly-Poly Poly-Region Region-Region)
Clearance DIFF_100E_INT [(InNetClass('LVDS') or InNetClass('CSI')) vs (OnLayer ('sig1') OR OnLayer('SIG2'))] p16: gap=8 ignorepadtopadclearanceinfootprint=TRUE except(1: Arc-Text Track-Text SMDPad-Text THPad-Text Via-Text Fill-Text Poly-Text Region-Text Text-Text; 5: Arc-Via Track-Via; 6: Via-Fill Via-Poly Via-Region; 9.5: Arc-Hole Track-Hole; 10: Via-Via Via-Hole Fill-Hole Poly-Hole Region-Hole; 12: Arc-THPad Track-THPad SMDPad-THPad SMDPad-Hole THPad-THPad THPad-Via THPad-Fill THPad-Poly THPad-Region THPad-Hole; 14.6: Arc-Arc Arc-Track Track-Track; 25: Fill-Fill Fill-Poly Fill-Region Poly-Poly Poly-Region Region-Region)
Clearance 2W_50E_INT [InNetClass('RGMII_TX_RX') AND (OnLayer('SIG1') OR OnLayer('SIG2'))] p17: gap=8 ignorepadtopadclearanceinfootprint=TRUE except(0: Track-Region SMDPad-Region Via-Region; 1: Arc-Text Track-Text SMDPad-Text THPad-Text Via-Text Fill-Text Poly-Text Region-Text Text-Text; 5: Arc-Via Track-Via; 5.5: Arc-Arc; 6: Via-Fill Via-Poly; 9.5: Arc-Hole Track-Hole; 10: Arc-THPad Track-THPad SMDPad-Fill SMDPad-Poly Via-Hole Fill-Poly Fill-Hole Poly-Hole Region-Hole; 11: Arc-Track Track-Track; 12: SMDPad-THPad SMDPad-Hole THPad-THPad THPad-Via THPad-Fill THPad-Poly THPad-Region THPad-Hole; 18: Via-Via; 25: Fill-Fill Fill-Region Poly-Poly Poly-Region Region-Region)
Clearance [All] p18: gap=8 ignorepadtopadclearanceinfootprint=TRUE except(0: SMDPad-Via; 1: Arc-Text Track-Text SMDPad-Text THPad-Text Via-Text Fill-Text Poly-Text Region-Text Text-Text; 5: Arc-Via Track-Via Via-Fill Via-Poly Via-Region; 5.5: Arc-Arc Arc-Track Track-Track; 7.7: Arc-SMDPad Track-SMDPad; 9: Arc-Hole Track-Hole; 10: Via-Hole Fill-Hole Poly-Hole Region-Hole; 12: SMDPad-THPad SMDPad-Hole THPad-THPad THPad-Via THPad-Fill THPad-Poly THPad-Region THPad-Hole; 18: Fill-Fill Fill-Poly Fill-Region Poly-Poly Poly-Region Region-Region)
Clearance Clearance_Poly_EXT [(InNetClass('PWR') AND OnLayer('Top Layer') AND ('Bottom Layer'))] p19: gap=12 ignorepadtopadclearanceinfootprint=TRUE except(0: SMDPad-Via; 1: Arc-Text Track-Text SMDPad-Text THPad-Text Via-Text Fill-Text Poly-Text Region-Text Text-Text Text-Hole; 6: Via-Fill Via-Poly Via-Region; 8: Arc-Arc Arc-Track Arc-SMDPad Track-Track Track-SMDPad SMDPad-SMDPad; 10: Arc-Via Arc-Hole Track-Via Track-Hole Via-Hole Fill-Hole Poly-Hole Region-Hole; 18: Via-Via Fill-Fill Fill-Poly Fill-Region Poly-Poly Poly-Region Region-Region)
Clearance DIFF_90E_INT [InDifferentialPairClass('DIFF_90E') vs OnLayer('SIG1')] p20: gap=8 ignorepadtopadclearanceinfootprint=TRUE except(0: SMDPad-Region Via-Region; 1: Arc-Text Track-Text SMDPad-Text THPad-Text Via-Text Fill-Text Poly-Text Region-Text Text-Text; 5: Arc-Via Track-Via; 6: Via-Fill Via-Poly; 9.5: Arc-Hole Track-Hole; 10: SMDPad-Fill SMDPad-Poly Via-Via Via-Hole Fill-Poly Fill-Hole Poly-Hole Region-Hole; 12: Arc-THPad Track-THPad SMDPad-THPad SMDPad-Hole THPad-THPad THPad-Via THPad-Fill THPad-Poly THPad-Region THPad-Hole; 15: Arc-Arc Arc-Track Track-Track; 25: Fill-Fill Fill-Region Poly-Poly Poly-Region Region-Region)
Clearance "SAME NET" [All] p21: gap=0 ignorepadtopadclearanceinfootprint=TRUE
Clearance EXT_S2S_12MIL [WithinRoom('S2S_12MIL') vs OnLayer('Bottom Layer')] p22: gap=6 ignorepadtopadclearanceinfootprint=TRUE except(1: Arc-Text Track-Text SMDPad-Text THPad-Text Via-Text Fill-Text Poly-Text Region-Text Text-Text; 5: Arc-Via Track-Via; 7: Via-Hole; 8: Arc-Hole Track-Hole SMDPad-SMDPad SMDPad-Fill SMDPad-Poly SMDPad-Region SMDPad-Hole Via-Via Fill-Hole Poly-Hole Region-Hole Text-Hole; 10: Fill-Fill Fill-Poly Fill-Region Poly-Poly Poly-Region Region-Region; 12: Arc-THPad Track-THPad SMDPad-THPad THPad-THPad THPad-Via THPad-Fill THPad-Poly THPad-Region THPad-Hole)
Clearance TRACE [InNetClass('TRACE') vs All and (not InNet('GND'))] p23: gap=8 ignorepadtopadclearanceinfootprint=TRUE except(1: Arc-Text Track-Text SMDPad-Text THPad-Text Via-Text Fill-Text Poly-Text Region-Text Text-Text; 5.5: Arc-Arc Arc-Track Track-Track; 6: Via-Fill Via-Poly Via-Region; 7: Arc-Via Track-Via; 7.7: Arc-SMDPad Track-SMDPad; 9: Arc-Hole Track-Hole; 10: Via-Via Via-Hole Fill-Hole Poly-Hole Region-Hole; 12: SMDPad-THPad SMDPad-Hole THPad-THPad THPad-Via THPad-Fill THPad-Poly THPad-Region THPad-Hole; 18: Fill-Fill Fill-Poly Fill-Region Poly-Poly Poly-Region Region-Region)
ComponentClearance ComponentClearance_MountingHoles_FiducialMarks [InComponentClass('Mounting Holes') vs InComponentClass('FiducialMark')] p1: gap=50 collisioncheckmode=3 verticalgap=10 showdistances=FALSE
ComponentClearance ComponentClearance_Shunt [InComponentClass('Header') vs InComponentClass('Shunt')] p2: gap=0 collisioncheckmode=3 verticalgap=0 showdistances=FALSE
ComponentClearance ComponentClearance_Logo [InComponentClass('Logo')] p3: gap=10 collisioncheckmode=3 verticalgap=10 showdistances=FALSE
ComponentClearance ComponentClearance_ScrewToNut [(HasFootprint('NY PMS 440 0025 PH')) vs (HasFootprint('Keystone_1902C'))] p4: gap=5 collisioncheckmode=3 verticalgap=10 showdistances=FALSE
ComponentClearance ComponentClearance_MountingHoles [InComponentClass('Mounting Holes')] p5: gap=250 collisioncheckmode=3 verticalgap=100000 showdistances=FALSE
ComponentClearance ComponentClearance_SmallPassives [HasFootprint('0201*') or  HasFootprint('0508') or HasFootprint('0603*') or HasFootprint('0612') or HasFootprint('0805*') or HasFootprint('0815*') or HasFootprint('0830*') or HasFootprint('1206*') or HasFootprint('1210*') or HasFootprint('1808*') or HasFootprint('1812*') or HasFootprint('1825*') or HasFootprint('2010*') or HasFootprint('2220*') or HasFootprint('2225*') or HasFootprint('2512*') or HasFootprint('2728*') or HasFootprint('3518*') vs HasFootprint('0201*') or HasFootprint('0508') or HasFootprint('0603*') or HasFootprint('0612') or HasFootprint('0805*') or HasFootprint('0815*') or HasFootprint('0830*') or HasFootprint('1206*') or HasFootprint('1210*') or HasFootprint('1808*') or HasFootprint('1812*') or HasFootprint('1825*') or HasFootprint('2010*') or HasFootprint('2220*') or HasFootprint('2225*') or HasFootprint('2512*') or HasFootprint('2728*') or HasFootprint('3518*')] p6: gap=5 collisioncheckmode=3 verticalgap=5 showdistances=FALSE
ComponentClearance ComponentClearance_THtoSMT [IsThruComponent vs IsSMTComponent] p7: gap=10 collisioncheckmode=3 verticalgap=10 showdistances=FALSE
ComponentClearance ComponentClearance_THtoTH [IsThruComponent vs IsThruComponent] p8: gap=20 collisioncheckmode=3 verticalgap=10 showdistances=FALSE
ComponentClearance [All] p9: gap=0 collisioncheckmode=3 verticalgap=0 showdistances=FALSE
ComponentClearance "TRIPAD COMPONENTS" [not InComponentClass('TRIPAD RESISTORS')] p10: gap=0 collisioncheckmode=3 verticalgap=0 showdistances=FALSE
DiffPairsRouting DiffPairsRouting_100E [InDifferentialPairClass('DIFF_100E')] p1: maxlimit=7.3 minlimit=1 mostfreqgap=7.3 toplayer_mingap=3.9 toplayer_maxgap=5 toplayer_prefgap=5 toplayer_minwidth=4 toplayer_maxwidth=5 toplayer_prefwidth=5 midlayer2_maxgap=1 midlayer2_prefgap=1 midlayer2_minwidth=1 midlayer2_maxwidth=1 midlayer2_prefwidth=1 midlayer3_maxgap=1 midlayer3_prefgap=1 midlayer3_minwidth=1 midlayer3_maxwidth=1 midlayer3_prefwidth=1 midlayer5_maxgap=1 midlayer5_prefgap=1 midlayer5_minwidth=1 midlayer5_maxwidth=1 midlayer5_prefwidth=1 midlayer6_mingap=7.3 midlayer6_minwidth=4.7 midlayer6_maxwidth=4.7 midlayer6_prefwidth=4.7 midlayer7_mingap=7.3 midlayer7_minwidth=4.7 midlayer7_maxwidth=4.7 midlayer7_prefwidth=4.7 midlayer8_maxgap=1 midlayer8_prefgap=1 midlayer8_minwidth=1 midlayer8_maxwidth=1 midlayer8_prefwidth=1 bottomlayer_mingap=6 bottomlayer_maxgap=6 bottomlayer_prefgap=6 bottomlayer_minwidth=4 bottomlayer_maxwidth=4 bottomlayer_prefwidth=4 substack1={9319A519-0D26-40B3-8AF8-C4998BECF1C7} toplayer_{9319a519-0d26-40b3-8af8-c4998becf1c7}_minwidth=15 toplayer_{9319a519-0d26-40b3-8af8-c4998becf1c7}_maxwidth=15 toplayer_{9319a519-0d26-40b3-8af8-c4998becf1c7}_prefwidth=15 midlayer2_{9319a519-0d26-40b3-8af8-c4998becf1c7}_minwidth=15 midlayer2_{9319a519-0d26-40b3-8af8-c4998becf1c7}_maxwidth=15 midlayer2_{9319a519-0d26-40b3-8af8-c4998becf1c7}_prefwidth=15 midlayer3_{9319a519-0d26-40b3-8af8-c4998becf1c7}_minwidth=15 midlayer3_{9319a519-0d26-40b3-8af8-c4998becf1c7}_maxwidth=15 midlayer3_{9319a519-0d26-40b3-8af8-c4998becf1c7}_prefwidth=15 midlayer5_{9319a519-0d26-40b3-8af8-c4998becf1c7}_minwidth=15 midlayer5_{9319a519-0d26-40b3-8af8-c4998becf1c7}_maxwidth=15 midlayer5_{9319a519-0d26-40b3-8af8-c4998becf1c7}_prefwidth=15 midlayer6_{9319a519-0d26-40b3-8af8-c4998becf1c7}_minwidth=15 midlayer6_{9319a519-0d26-40b3-8af8-c4998becf1c7}_maxwidth=15 midlayer6_{9319a519-0d26-40b3-8af8-c4998becf1c7}_prefwidth=15 midlayer7_{9319a519-0d26-40b3-8af8-c4998becf1c7}_minwidth=15 midlayer7_{9319a519-0d26-40b3-8af8-c4998becf1c7}_maxwidth=15 midlayer7_{9319a519-0d26-40b3-8af8-c4998becf1c7}_prefwidth=15 midlayer8_{9319a519-0d26-40b3-8af8-c4998becf1c7}_minwidth=15 midlayer8_{9319a519-0d26-40b3-8af8-c4998becf1c7}_maxwidth=15 midlayer8_{9319a519-0d26-40b3-8af8-c4998becf1c7}_prefwidth=15 bottomlayer_{9319a519-0d26-40b3-8af8-c4998becf1c7}_minwidth=15 bottomlayer_{9319a519-0d26-40b3-8af8-c4998becf1c7}_maxwidth=15 bottomlayer_{9319a519-0d26-40b3-8af8-c4998becf1c7}_prefwidth=15 maxuncoupledlength=230
DiffPairsRouting DiffPairsRouting_90E [InDifferentialPairClass('DIFF_90E')] p2: maxlimit=6.5 minlimit=1 mostfreqgap=6.5 toplayer_mingap=4 toplayer_maxgap=4 toplayer_prefgap=4 toplayer_minwidth=6 toplayer_maxwidth=6 toplayer_prefwidth=6 midlayer2_maxgap=1 midlayer2_prefgap=1 midlayer2_minwidth=1 midlayer2_maxwidth=1 midlayer2_prefwidth=1 midlayer3_maxgap=1 midlayer3_prefgap=1 midlayer3_minwidth=1 midlayer3_maxwidth=1 midlayer3_prefwidth=1 midlayer5_maxgap=1 midlayer5_prefgap=1 midlayer5_minwidth=1 midlayer5_maxwidth=1 midlayer5_prefwidth=1 midlayer6_mingap=6.5 midlayer6_minwidth=5.5 midlayer6_maxwidth=5.5 midlayer6_prefwidth=5.5 midlayer7_mingap=6.5 midlayer7_minwidth=5.5 midlayer7_maxwidth=5.5 midlayer7_prefwidth=5.5 midlayer8_maxgap=1 midlayer8_prefgap=1 midlayer8_minwidth=1 midlayer8_maxwidth=1 midlayer8_prefwidth=1 bottomlayer_mingap=5.8 bottomlayer_maxgap=5.8 bottomlayer_prefgap=5.8 bottomlayer_minwidth=5 bottomlayer_maxwidth=5 bottomlayer_prefwidth=5 substack1={9319A519-0D26-40B3-8AF8-C4998BECF1C7} toplayer_{9319a519-0d26-40b3-8af8-c4998becf1c7}_minwidth=15 toplayer_{9319a519-0d26-40b3-8af8-c4998becf1c7}_maxwidth=15 toplayer_{9319a519-0d26-40b3-8af8-c4998becf1c7}_prefwidth=15 midlayer2_{9319a519-0d26-40b3-8af8-c4998becf1c7}_minwidth=15 midlayer2_{9319a519-0d26-40b3-8af8-c4998becf1c7}_maxwidth=15 midlayer2_{9319a519-0d26-40b3-8af8-c4998becf1c7}_prefwidth=15 midlayer3_{9319a519-0d26-40b3-8af8-c4998becf1c7}_minwidth=15 midlayer3_{9319a519-0d26-40b3-8af8-c4998becf1c7}_maxwidth=15 midlayer3_{9319a519-0d26-40b3-8af8-c4998becf1c7}_prefwidth=15 midlayer5_{9319a519-0d26-40b3-8af8-c4998becf1c7}_minwidth=15 midlayer5_{9319a519-0d26-40b3-8af8-c4998becf1c7}_maxwidth=15 midlayer5_{9319a519-0d26-40b3-8af8-c4998becf1c7}_prefwidth=15 midlayer6_{9319a519-0d26-40b3-8af8-c4998becf1c7}_minwidth=15 midlayer6_{9319a519-0d26-40b3-8af8-c4998becf1c7}_maxwidth=15 midlayer6_{9319a519-0d26-40b3-8af8-c4998becf1c7}_prefwidth=15 midlayer7_{9319a519-0d26-40b3-8af8-c4998becf1c7}_minwidth=15 midlayer7_{9319a519-0d26-40b3-8af8-c4998becf1c7}_maxwidth=15 midlayer7_{9319a519-0d26-40b3-8af8-c4998becf1c7}_prefwidth=15 midlayer8_{9319a519-0d26-40b3-8af8-c4998becf1c7}_minwidth=15 midlayer8_{9319a519-0d26-40b3-8af8-c4998becf1c7}_maxwidth=15 midlayer8_{9319a519-0d26-40b3-8af8-c4998becf1c7}_prefwidth=15 bottomlayer_{9319a519-0d26-40b3-8af8-c4998becf1c7}_minwidth=15 bottomlayer_{9319a519-0d26-40b3-8af8-c4998becf1c7}_maxwidth=15 bottomlayer_{9319a519-0d26-40b3-8af8-c4998becf1c7}_prefwidth=15 maxuncoupledlength=200
DiffPairsRouting DiffPairsRouting_120E [InDifferentialPairClass('DIFF_120E')] p3: maxlimit=14 minlimit=1 mostfreqgap=1 toplayer_mingap=12 toplayer_maxgap=12 toplayer_prefgap=12 toplayer_minwidth=5.5 toplayer_maxwidth=5.5 toplayer_prefwidth=5.5 midlayer2_maxgap=1 midlayer2_minwidth=1 midlayer2_maxwidth=1 midlayer2_prefwidth=1 midlayer3_maxgap=1 midlayer3_minwidth=1 midlayer3_maxwidth=1 midlayer3_prefwidth=1 midlayer5_maxgap=1 midlayer5_minwidth=1 midlayer5_maxwidth=1 midlayer5_prefwidth=1 midlayer6_maxgap=1 midlayer6_minwidth=1 midlayer6_maxwidth=1 midlayer6_prefwidth=1 midlayer7_maxgap=1 midlayer7_minwidth=1 midlayer7_maxwidth=1 midlayer7_prefwidth=1 midlayer8_maxgap=1 midlayer8_minwidth=1 midlayer8_maxwidth=1 midlayer8_prefwidth=1 bottomlayer_mingap=14 bottomlayer_prefgap=14 bottomlayer_minwidth=4 bottomlayer_maxwidth=4 bottomlayer_prefwidth=4 substack1={9319A519-0D26-40B3-8AF8-C4998BECF1C7} toplayer_{9319a519-0d26-40b3-8af8-c4998becf1c7}_minwidth=15 toplayer_{9319a519-0d26-40b3-8af8-c4998becf1c7}_maxwidth=15 toplayer_{9319a519-0d26-40b3-8af8-c4998becf1c7}_prefwidth=15 midlayer2_{9319a519-0d26-40b3-8af8-c4998becf1c7}_minwidth=15 midlayer2_{9319a519-0d26-40b3-8af8-c4998becf1c7}_maxwidth=15 midlayer2_{9319a519-0d26-40b3-8af8-c4998becf1c7}_prefwidth=15 midlayer3_{9319a519-0d26-40b3-8af8-c4998becf1c7}_minwidth=15 midlayer3_{9319a519-0d26-40b3-8af8-c4998becf1c7}_maxwidth=15 midlayer3_{9319a519-0d26-40b3-8af8-c4998becf1c7}_prefwidth=15 midlayer5_{9319a519-0d26-40b3-8af8-c4998becf1c7}_minwidth=15 midlayer5_{9319a519-0d26-40b3-8af8-c4998becf1c7}_maxwidth=15 midlayer5_{9319a519-0d26-40b3-8af8-c4998becf1c7}_prefwidth=15 midlayer6_{9319a519-0d26-40b3-8af8-c4998becf1c7}_minwidth=15 midlayer6_{9319a519-0d26-40b3-8af8-c4998becf1c7}_maxwidth=15 midlayer6_{9319a519-0d26-40b3-8af8-c4998becf1c7}_prefwidth=15 midlayer7_{9319a519-0d26-40b3-8af8-c4998becf1c7}_minwidth=15 midlayer7_{9319a519-0d26-40b3-8af8-c4998becf1c7}_maxwidth=15 midlayer7_{9319a519-0d26-40b3-8af8-c4998becf1c7}_prefwidth=15 midlayer8_{9319a519-0d26-40b3-8af8-c4998becf1c7}_minwidth=15 midlayer8_{9319a519-0d26-40b3-8af8-c4998becf1c7}_maxwidth=15 midlayer8_{9319a519-0d26-40b3-8af8-c4998becf1c7}_prefwidth=15 bottomlayer_{9319a519-0d26-40b3-8af8-c4998becf1c7}_minwidth=15 bottomlayer_{9319a519-0d26-40b3-8af8-c4998becf1c7}_maxwidth=15 bottomlayer_{9319a519-0d26-40b3-8af8-c4998becf1c7}_prefwidth=15 maxuncoupledlength=270
FabricationTestPointUsage TestPointUsage [All] p1: valid=2 allowmultiple=FALSE
FabricationTestpoint Testpoint [All] p1: side=3 testpointundercomponent=TRUE minsize=40 maxsize=100 preferedsize=60 minholesize=0 maxholesize=40 preferedholesize=32 testpointgrid=1 allowsidetop=TRUE allowsidebottom=TRUE usegrid=TRUE gridtolerance=0.01
FanoutControl Fanout_LCC [IsLCC] p1: bgadir=Out bgaviamode=Centered fanoutstyle=Auto fanoutdirection=Alternating viagrid=1 // Fanout_LCC (Default Rule)
FanoutControl Fanout_BGA [IsBGA] p2: bgadir=Out bgaviamode=Centered fanoutstyle=Auto fanoutdirection=Alternating viagrid=1 // Fanout_BGA (Default Rule)
FanoutControl Fanout_Default [All] p4: bgadir=Out bgaviamode=Centered fanoutstyle=Auto fanoutdirection=Alternating viagrid=1 // Fanout_Default (Default Rule)
FanoutControl Fanout_Small [(CompPinCount < 5)] p5: bgadir=Out bgaviamode=Centered fanoutstyle=Auto fanoutdirection=OutThenIn viagrid=1 // Fanout_Small (Default Rule)
HoleSize [All] p1: absolutevalues=TRUE maxlimit=251 minlimit=5.9 maxpercent=80.000 minpercent=20.000
HoleToHoleClearance [All] p1: gap=5 allowstackedmicrovias=TRUE
MatchedLengths RGMII_TX [InxSignalClass('RGMII_Tx')] p1: tolerance=12.5 checknetsindiffpair=FALSE checkdiffpairvsdiffpair=TRUE checkxsignals=TRUE checkothers=TRUE
MatchedLengths RGMII_RX [InxSignalClass('RGMII_Rx')] p2: tolerance=12.5 checknetsindiffpair=FALSE checkdiffpairvsdiffpair=TRUE checkxsignals=TRUE checkothers=TRUE
MatchedLengths Trace_Data [InxSignalClass('Trace')] p3: tolerance=50 checknetsindiffpair=FALSE checkdiffpairvsdiffpair=TRUE checkxsignals=TRUE checkothers=TRUE
MatchedLengths TD [InxSignalClass('TD')] p4: tolerance=12.5 checknetsindiffpair=FALSE checkdiffpairvsdiffpair=TRUE checkxsignals=TRUE checkothers=TRUE
MatchedLengths LVDS_diff [InDifferentialPairClass('LVDS')] p5: tolerance=5 checknetsindiffpair=TRUE checkdiffpairvsdiffpair=FALSE checkxsignals=FALSE checkothers=FALSE
MatchedLengths LVDS [InxSignalClass('LVDS_TX')] p6: tolerance=12.5 checknetsindiffpair=FALSE checkdiffpairvsdiffpair=TRUE checkxsignals=TRUE checkothers=TRUE
MatchedLengths CSI2 [InxSignalClass('CSI2')] p7: tolerance=12.5 checknetsindiffpair=FALSE checkdiffpairvsdiffpair=TRUE checkxsignals=TRUE checkothers=TRUE
MinimumAnnularRing MinimumAnnularRing_ThermalPadVias [IsVia and InAnyComponent] p1: minimumring=5
MinimumAnnularRing [All] p2 off: minimumring=6
MinimumSolderMaskSliver MinimumSolderMaskSliver_Logo [InComponentClass('Logo') vs InComponentClass('Logo')] p1: minsoldermaskwidth=0.7
MinimumSolderMaskSliver [All] p2: minsoldermaskwidth=3
PlaneConnect [All] p1: planeconnectstyle=Relief reliefexpansion=10 reliefentries=4 reliefconductorwidth=10 reliefairgap=10
PolygonConnect PolygonConnect_3 [All] p1: connectstyle=Direct reliefconductorwidth=10 reliefentries=4 polygonreliefangle="90 Angle" airgapwidth=10
PolygonConnect PolygonConnect_2 [All vs IsNamedPolygon('Top Layer-AGND 1')] p2: connectstyle=Direct reliefconductorwidth=10 reliefentries=4 polygonreliefangle="90 Angle" airgapwidth=10
PolygonConnect PolygonConnect_1 [All vs IsNamedPolygon('NONET_L06_P304')] p3: connectstyle=Direct reliefconductorwidth=10 reliefentries=4 polygonreliefangle="90 Angle" airgapwidth=10
PolygonConnect [All] p4: connectstyle=Direct reliefconductorwidth=10 reliefentries=4 polygonreliefangle="90 Angle" airgapwidth=10
RoomDefinition BGA [False] p1: confinementstyle=ConfineIn formatcopy=TRUE lockcomponents=FALSE outline 1227.35,702.68 1838.58,702.68 1838.58,1248.46 1227.35,1248.46
RoutingVias ThermalPadVias [IsVia and InAnyComponent] p1: holewidth=8 width=18 viastyle="Through Hole" minholewidth=7.87 minwidth=18 maxholewidth=22 maxwidth=22
RoutingVias [All] p2: holewidth=8 width=18 viastyle="Through Hole" minholewidth=5.9 minwidth=13.77 maxholewidth=20 maxwidth=32
SMDEntry [All] p1: side=TRUE corner=FALSE anyangle=TRUE
SMDToCorner [All] p1: distance=0
SilkToBoardRegionClearance [Not ((IsComment or IsDesignator) And (Hide <> 'False')) and not InRegion(1000,500,4000,800)] p1:
SilkToSilkClearance SilkToSilkClearance_Pb-FreeLogo [(HasFootprint('Pb-Free_Overlay_Medium') OR HasFootprint('Pb-Free_Overlay_Small')) vs (HasFootprint('Pb-Free_Overlay_Medium') OR HasFootprint('Pb-Free_Overlay_Small'))] p1: silktosilkclearance=0
SilkToSilkClearance [All] p2: silktosilkclearance=0
SilkToSolderMaskClearance SilkToComponentPadClearance [(IsPad or IsFill or IsRegion) and InAnycomponent] p1: minsilkscreentomaskgap=0 clearancetoexposedcopper=TRUE
SilkToSolderMaskClearance "Silk to Solder Mask Opening" [All] p2: minsilkscreentomaskgap=0 clearancetoexposedcopper=FALSE
SolderMaskExpansion [All] p1: expansion=1.97 istentingtop=FALSE
UnRoutedNet [All] p1: checkbadconnections=TRUE
Width Antenna [(InNetClass('RX')or InNetClass('TX'))] p1: maxlimit=10 minlimit=8.4 preferedwidth=10 toplayer_maxwidth=8.4 toplayer_prefwidth=8.4 midlayer2_minwidth=10 midlayer3_minwidth=10 midlayer5_minwidth=10 midlayer6_minwidth=10 midlayer7_minwidth=10 midlayer8_minwidth=10 bottomlayer_minwidth=10 substack1={9319A519-0D26-40B3-8AF8-C4998BECF1C7} minimp=50.000000 maximp=50.000000 favimp=50.000000
Width POWER [InNetClass('PWR')] p2: maxlimit=100 minlimit=1 preferedwidth=10 toplayer_maxwidth=50 midlayer2_minwidth=4 midlayer3_minwidth=4 midlayer5_minwidth=4 midlayer6_minwidth=4 midlayer7_minwidth=4 midlayer8_minwidth=4 bottomlayer_minwidth=7 bottomlayer_maxwidth=50 substack1={9319A519-0D26-40B3-8AF8-C4998BECF1C7} minimp=50.000000 maximp=50.000000 favimp=50.000000 checkconnectedcopper=TRUE
Width [All] p3: maxlimit=100 minlimit=4 preferedwidth=10 toplayer_maxwidth=70 toplayer_prefwidth=10.6 midlayer2_minwidth=10 midlayer3_minwidth=10 midlayer5_minwidth=10 midlayer6_minwidth=5.5 midlayer6_maxwidth=30 midlayer6_prefwidth=5.5 midlayer7_minwidth=5.5 midlayer7_maxwidth=15 midlayer7_prefwidth=5.5 midlayer8_minwidth=10 bottomlayer_maxwidth=70 bottomlayer_prefwidth=8.3 substack1={9319A519-0D26-40B3-8AF8-C4998BECF1C7} minimp=50.000000 maximp=50.000000 favimp=50.000000 checkconnectedcopper=TRUE
13 further rules are at their usual default settings.

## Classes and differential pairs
net class CAN_DIFF: CAN1H CAN1L
net class RGMII: ETH_TRD_N ETH_TRD_P NetR230_2 NetR234_2
component class PROC113D_Ethernet: C32 C35 C40 C44 C51 C52 C95 C121 C157 C161 C167 D15 D17 FB1 L7 R1 R4 R5 R34 R50 R51 R74 R79 R89 R96 R100 R178 R225 R230 R234 R237 R238 R239 R240 R242 R245 R246 R247 R248 R249 R251 R253 R254 R255 R256 R257 R265 R270 R275 R281 R282 R350 U15 YE7
net class Antenna: RX1 RX2 RX3 RX4 TX1 TX2 TX3 TX4
net class RESET: AR_NRST AR_WRMRST
net class GPIO: GPIO_3 GPIO_4 GPIO_8 GPIO_9 GPIO_30 GPIO_31 MSS_GPIO_0 MSS_GPIO_1 MSS_GPIO_2 MSS_GPIO_11 MSS_GPIO_28 VPP_EN
net class EPWM: MSS_EPWMA0 MSS_EPWMA1 MSS_EPWMB0
net class 40MHz_CLK: GND XTALM XTALP
net class MSS_SPIB: MSS_SPIB_CLK MSS_SPIB_CS0 MSS_SPIB_CS1 MSS_SPIB_MISO MSS_SPIB_MOSI SOP1_MSS_SPIB_CS2
net class MSS_SPIA: MSS_SPIA_CLK MSS_SPIA_CS0 MSS_SPIA_HOSTIRQ MSS_SPIA_MISO MSS_SPIA_MOSI
net class RGMII_TX_RX: MSS_RGMII_RCLK MSS_RGMII_RCTL MSS_RGMII_RD0 MSS_RGMII_RD1 MSS_RGMII_RD2 MSS_RGMII_RD3 MSS_RGMII_TCLK MSS_RGMII_TCTL MSS_RGMII_TD0 MSS_RGMII_TD1 MSS_RGMII_TD2 MSS_RGMII_TD3
component class PROC113D_power_Supply: C1 C41 C145 C149 CP8 Cu1 Cu2 Cu3 Cu4 Cu5 Cu6 Cu7 D8 D14 D16 Dr8 Dr9 L3 L4 P1 R7 R8 R12 R56 R57 R58 R103 R159 R332 R409 TVS2 U6 U27
net class UART: BSS_UARTA_TX DSS_UARTA_RX DSS_UARTA_TX MSS_RS232RX MSS_RS232TX MSS_UARTA_RX SOP3_MSS_UARTB_TX SOP4_MSS_UARTA_TX
net class PWR: NetC11_2 NetC13_2 NetC90_2 NetC149_2 VPP_1P7
net class MDIO: MSS_MDIO_CLK MSS_MDIO_DATA
net class I2C: MSS_I2CA_SCL MSS_I2CA_SDA
net class QSPI: AR_QSPI_CLK AR_QSPI_CS AR_QSPI_D0 AR_QSPI_D1 AR_QSPI_D2 AR_QSPI_D3 QSPI_D0_FLASH QSPI_D1_FLASH QSPI_D2_FLASH QSPI_D3_FLASH QSPI_SCLK_FLASH
net class LVDS: LVDS_TX0_N LVDS_TX0_P LVDS_TX1_N LVDS_TX1_P LVDS_TX2_CLK_N LVDS_TX2_CLK_P LVDS_TX3_FRCLK_N LVDS_TX3_FRCLK_P
net class JTAG: NetR386_2 SOP0_TDO TCK TDI TMS
net class CSI: CSI2_RX0_0_N CSI2_RX0_0_P CSI2_RX0_1_N CSI2_RX0_1_P CSI2_RX0_CLK_N CSI2_RX0_CLK_P
net class GPADC: GND GPADC1 GPADC2 GPADC3 GPADC4 GPADC5 GPADC6 GPADC7 GPADC8 GPADC9
net class CAN: CAN1H CAN1L MSS_MCANA_RX MSS_MCANA_TX MSS_MCANB_RX MSS_MCANB_TX NetC13_2 NetR21_2 NetR25_2
component class PROC113D_IO_Reference: C106 C108 C131 C135 C136 J14 R3 R22 R23 R31 R133 R156 R172 R218 R233 R271 R272 R273 R276 R277 R278 R279 R280 R315 R316 R326 R380 R381 R386 R392 U29 Y3
component class PROC113D_Decoupling_Reference: C5 C92 C96 C102 C103 C107 C110 C111 C112 C113 C114 C115 C116 C117 C137 C138 C139 C140 C141 C142 C146 C150 C163 C164 C165 C168 C170 C172 C174 C175 C176 C177 C179 C180 C181
component class PROC113D_CAN_SOP: C11 C12 C13 C80 C128 CN1 D4 J1 P11 PDB1 PL1 PSO1 R15 R16 R18 R21 R24 R25 R52 R53 R54 R55 R110 R309 R312 RC31 RC32 RC33 RCN1 RCN2 RCN3 RCN4 RCN5 RCN11 RCN12 RCN13 RCN14 RCN15 RCN17 RCN18 RCN19 RCN24 RCN25 Rs301 Rs303 TRS1 U5 UCAN1
component class PROC113D_Flash_LED_GPS: ATA3 C8G C90 C91 C105 CBG1 CGP2 D6 D12 D13 DS2 J10 J11 L11 MAX-M8Q Q1 R8G R37 R40 R43 R44 R45 R46 R47 R48 R49 R61 R262 R263 R264 R266 R267 R331 R333 R334 R335 R347 RG1 RG9 RGP1 RGP2 U9
component class PROC113D_PMIC_Reference: C3 C6 C7 C8 C9 C31 C58 C120 C123 C124 C125 C129 C130 C132 C134 C143 C144 C153 C199 C200 C201 C202 L1 L2 L8 L9 L10 NT1 NT2 NT3 NT4 R11 R14 R17 R30 R63 R71 R73 R75 R76 R99 R102 R104 R106 R111 R116 R125 R186 R190 R193 R200 R210 R291 R292 TP8 U8
component class Header: P1 PSO1
differential pair TRD3: +TRD3_P -TRD3_N
differential pair TRD2: +TRD2_P -TRD2_N
differential pair TRD1: +TRD1_P -TRD1_N
differential pair ETH_TRD: +ETH_TRD_P -ETH_TRD_N

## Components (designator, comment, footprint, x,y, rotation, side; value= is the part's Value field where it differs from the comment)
ATA3 "SMA" SMB-ATA3 3517.91,398.22 r180 bottom
C1 "104" 0805 2989,593 r270 top
C3 "GCM188R70J225KE22D" 0603L 311.26,838.07 r0 bottom value=2.2uF
C5 "GCM155R71C224KE02D" 0402 1392.98,1182.61 r270 bottom value=0.22uF
C6 "GCJ188C70J475KE02J" FP-GCJ188C70J475KE02J_0603-MFG 490.13,535.78 r180 bottom value=4.7µF
C7 "GCM21BR71A106KE22L" 0805L 581.96,1054.02 r90 top value=10uF
C8 "GCJ188C70J475KE02J" FP-GCJ188C70J475KE02J_0603-MFG 623.87,477.54 r90 bottom value=4.7µF
C8G "103" 0603 3113.7,235.33 r90 top
C9 "NFM18HC105C1C3D" FP-NFM18HC105C1C3D_0603-MFG 520.42,632.2 r180 bottom
C11 "GCM155R71C104KA55D" 0603 3005.59,2081.08 r0 bottom value=0.1uF
C12 "GCM155R71C104KA55D" 0603 3181.01,2076.08 r270 bottom value=0.1uF
C13 "GCM155R71H472KA37D" 0603 3046.85,1336.34 r180 bottom value=4700pF
C31 "GCM21BR71A106KE22L" 0805L 490.7,472.45 r0 top value=10uF
C32 "CGA3E3X7R1H474K080AE" 0603 690.45,1669.76 r270 top value=0.47uF
C35 "CGA2B3X7R1H103K050BB" 0402 741.96,1598.79 r0 top value=0.01uF
C40 "CGA3E3X7R1H474K080AE" 0603 951.07,1986.7 r0 bottom value=0.47uF
C41 "104" 0805 2624.28,781.75 r180 top
C44 "CGA2B3X7R1H103K050BB" 0402 1020.26,1936.25 r270 bottom value=0.01uF
C51 "CGA3E3X7R1H474K080AE" 0603 737.88,2115.52 r90 top value=0.47uF
C52 "CGA2B3X7R1H103K050BB" 0402 781.2,2184.86 r180 top value=0.01uF
C58 "NFM18HC105C1C3D" FP-NFM18HC105C1C3D_0603-MFG 517.53,984.66 r180 bottom
C80 "CGA2B3X7R1H104K050BB" 0603 3110.04,1493.73 r270 bottom value=0.1uF
C90 "GCM188R71C105KA64D" 0603 402.07,1452.2 r180 top value=1uF
C91 "CGA2B3X7R1H104K050BB" 0603 401.8,1394.2 r180 top value=0.1uF
C92 "GCM155R71C224KE02D" 0402 1199.75,1030.94 r90 top value=0.22uF
C95 "15pF" 0603 382.71,2039.65 r180 bottom value=100pF
C96 "GCM155R71C224KE02D" 0402 1244.11,918.6 r0 bottom value=0.22uF
C102 "GRT155R70J105KE01D" FP-GRT155R70J105KE01D_0402-MFG 1624.94,1132.56 r270 bottom
C103 "GRT155R70J105KE01D" FP-GRT155R70J105KE01D_0402-MFG 1574.92,1083.01 r270 bottom
C105 "GCM155R71C104KA55D" 0603 888.25,516.71 r0 top value=0.1uF
C106 "GRM1555C1H3R9CA01D" 0402 1804.28,1285.76 r90 top value=3.9pF
C107 "GCM155R71C224KE02D" 0402 1455.53,1236.19 r0 bottom value=0.22uF
C108 "GRM1555C1H3R9CA01D" 0402 1789.5,1280.23 r270 top value=3.9pF
C110 "GCM21BR71A106KE22L" 0805L 1753.74,1037.54 r0 bottom value=10uF
C111 "GCM155R71C224KE02D" 0603 1691.51,1188.85 r180 bottom value=0.22uF
C112 "GCM21BR71A106KE22L" 0805L 1411.17,1329.75 r90 bottom value=10uF
C113 "GCM155R71C224KE02D" 0402 1423.36,1231.72 r0 bottom value=0.22uF
C114 "GCM21BR71A106KE22L" 0805L 1498.29,1219.68 r90 bottom value=10uF
C115 "GCM155R71C224KE02D" 0603 1498.51,1223.9 r270 bottom value=0.22uF
C116 "GCM21BR71A106KE22L" 0805L 1695.6,1102.9 r90 bottom value=10uF
C117 "GCM155R71C224KE02D" 0402 1699.38,1048.91 r180 bottom value=0.22uF
C120 "GCM21BR71A106KE22L" 0805L 757.23,535.78 r0 top value=10uF
C121 "15pF" 0603 331.35,1801.51 r0 bottom value=100pF
C123 "GCM188R70J225KE22D" 0603L 303.22,775.43 r0 bottom value=2.2uF
C124 "GCJ188C70J475KE02J" FP-GCJ188C70J475KE02J_0603-MFG 688.49,762.25 r270 bottom value=4.7µF
C125 "CGA4J1X7T0J226M" 0805_155 660.78,1118.07 r90 bottom value=22uF
C128 "CGA2B3X7R1H104K050BB" 0603 3455.11,2092.27 r90 bottom value=0.1uF
C129 "CGA4J1X7T0J226M" 0805_155 355.69,457.56 r270 bottom value=22uF
C130 "CGA4J1X7T0J226M" 0805_155 277.37,455.95 r270 bottom value=22uF
C131 "GCM155R71C104KA55D" 0603 1305.32,1578.4 r270 bottom value=0.1uF
C132 "CGA4J1X7T0J226M" 0805_155 374.64,1118.07 r90 bottom value=22uF
C134 "CGA4J1X7T0J226M" 0805_155 289.15,1128.43 r90 bottom value=22uF
C135 "GCM155R71C104KA55D" 0603 1187.05,1578.3 r270 bottom value=0.1uF
C136 "GCM155R71C104KA55D" 0603 1071.79,1316.91 r0 bottom value=0.1uF
C137 "GCM188R70J225KE22D" 0603 1147.2,1076.39 r0 top value=2.2uF
C138 "GCM155R71C224KE02D" 0402 1347.4,930.98 r90 bottom value=0.22uF
C139 "GCM155R71C224KE02D" 0402 1424.81,1067.96 r0 bottom value=0.22uF
C140 "GCM155R71C224KE02D" 0402 1571.32,830.71 r180 bottom value=0.22uF
C141 "GCM155R71C224KE02D" 0402 1524.39,829.54 r180 bottom value=0.22uF
C142 "GCM155R71C224KE02D" 0402 1412.68,879.6 r90 bottom value=0.22uF
C143 "CGA4J1X7T0J226M" 0805_155 385.5,156.43 r180 bottom value=22uF
C144 "GCJ188C70J475KE02J" FP-GCJ188C70J475KE02J_0603-MFG 569.8,1094.46 r270 bottom value=4.7µF
C145 "GCM188R71C105KA64D" 0603L 2466.73,453.52 r180 bottom value=1uF
C146 "GCM188R70J225KE22D" 0603L 1188.42,856.98 r90 bottom value=2.2uF
C149 "GCM188R70J225KE22D" 0603L 2350.97,755.76 r270 bottom value=2.2uF
C150 "GCM155R71C104KA55D" 0402 1237.46,1137.96 r90 top value=0.1uF
C153 "GCJ188C70J475KE02J" FP-GCJ188C70J475KE02J_0603-MFG 462.18,1094.46 r270 bottom value=4.7µF
C157 "CGA4J2X7R2A104K125AA" 0805 937.9,2314.65 r180 bottom value=0.1uF
C161 "CGA4J2X7R2A104K125AA" 0805 937.9,2402.95 r180 bottom value=0.1uF
C163 "GCM155R71C224KE02D" 0402 1209.16,974.19 r90 top value=0.22uF
C164 "GCM155R71C224KE02D" 0402 1536.52,700.69 r180 bottom value=0.22uF
C165 "GCM155R71C224KE02D" 0402 1498.24,728.58 r180 bottom value=0.22uF
C167 "GRM31BR73A472KW01L" 1206 652.54,2400.68 r180 top value=4700pF
C168 "GCM155R71C224KE02D" 0402 1627.61,1028.74 r0 bottom value=0.22uF
C170 "GCM155R71C224KE02D" 0402 1705.93,760.31 r270 bottom value=0.22uF
C172 "GCM155R71C224KE02D" 0402 1351.03,774.96 r270 bottom value=0.22uF
C174 "GCM155R71C224KE02D" 0402 1317.74,1063.86 r0 bottom value=0.22uF
C175 "GCM155R71C224KE02D" 0603 1805.28,679.1 r180 bottom value=0.22uF
C176 "GCM155R71C224KE02D" 0402 1732.84,848.28 r180 bottom value=0.22uF
C177 "GCM155R71C224KE02D" 0402 1332.19,768.06 r90 bottom value=0.22uF
C179 "NFM18HC105C1C3D" FP-NFM18HC105C1C3D_0603-MFG 1063.02,1305.06 r180 top
C180 "CGA2B3X7R1H473K050BB" 0402 1520.73,1030.82 r180 bottom value=0.047uF
C181 "NFM18HC105C1C3D" FP-NFM18HC105C1C3D_0603-MFG 1643.93,1057.19 r270 bottom
C199 "GCM155R71C224KE02D" 0603 484.08,455.32 r0 top value=0.22uF
C200 "GCM155R71C104KA55D" 0603 500.23,454.33 r0 bottom value=0.1uF
C201 "CGA4J1X7T0J226M" 0805_155 384.02,236 r180 bottom value=22uF
C202 "CGA4J1X7T0J226M" 0805_155 384.8,313.25 r180 bottom value=22uF
CBG1 "100uF/10V" 100uF 2656.45,661.76 r90 bottom
CGP2 "104" 0603 2695.45,333.76 r90 bottom
CN1 "1nF" 0805 3025.64,2277.83 r180 bottom
CP8 "47UF/10V" 100uF 2288.11,254.74 r90 bottom
Cu1 "NC.475" 0603 3204.47,763.92 r270 bottom
Cu2 "102" 0603 2434.59,242.18 r90 bottom
Cu3 "224" 0603 3267.55,713.24 r90 bottom
Cu4 "104" 0603 3141.72,763.92 r270 bottom
Cu5 "47uF/50V" "CAP.2/.4 - duplicate" 3491,619 r270 top
Cu6 "475" 0603 3063.21,1249.17 r180 top
Cu7 "475" 0603 3355,836 r0 top
D4 "SMS3923-040LF" SOD-882 2743.49,1329.62 r90 bottom value=V
D6 "SML-LXT0805GW-TR" LED1 2301.61,784.97 r90 top value=Green
D8 "ES1D" DIOD-ES1D 2713.04,532.95 r270 top
D12 "SML-LXT0805GW-TR" LED1 1821.7,378.66 r90 top value=Green
D13 "SML-E12Y8WT86" LED1 2098.45,300.76 r0 top value=Yellow
D14 "SML-LXT0805GW-TR" LED1 2839.45,1072.76 r180 top value=Green
D15 "TPD1E05U06QDPYRQ1" 0402 994.98,2238.49 r180 bottom
D16 "SML-LXT0805GW-TR" LED1 2722.45,130.85 r270 top value=Green
D17 "TPD1E05U06QDPYRQ1" 0402 999.2,2469 r0 bottom
Dr8 "SK16" DIOD-ES1D 3245.27,1376.59 r0 top
Dr9 "SK16" DIOD-ES1D 3127.17,1377.85 r0 top
DS2 "LS L29K-G1J2-1-Z" LED1 97.34,759.66 r0 top value=Red
FB1 "BLM18AG102SH1D" 0603 598.8,2148.64 r90 top
J1 "0" SIP2 3339.05,1940.42 r0 top
J10 "SWITH" SIP2 2264.47,579.04 r90 top
J11 "SWITH" SIP2 940.82,380.84 r0 top
J14 "128-0711-201" Johnson_128-0711-201 2118.21,775.03 r0 top
L1 "TFM201610ALMA1R5MTAA" 2016 540.06,583.74 r0 top value=1.5uH
L2 "TFM201610ALMAR24MTAA" "FP-TFM201610ALMAR24MTAA_0806 (2016 Metric)-MFG" 355.03,565.35 r270 bottom value=0.24uH
L3 "47uH" "L=47UH - small" 2488.56,454.95 r270 top
L4 "4.7uH" "L=47UH - small" 3193.99,1051.75 r270 top
L7 "ACT1210L-201-2P-TL00" ACT1210L-201-2P-TL00 700.37,2449.69 r0 bottom
L8 "TFM201610ALMAR24MTAA" "FP-TFM201610ALMAR24MTAA_0806 (2016 Metric)-MFG" 374.91,1008.67 r90 bottom value=0.24uH
L9 "TFM201610ALMAR24MTAA" "FP-TFM201610ALMAR24MTAA_0806 (2016 Metric)-MFG" 658.2,1003.85 r90 bottom value=0.24uH
L10 "XAL4030-472MEB" XAL4030 549.41,304.27 r180 bottom value=4.7uH
L11 "0402CS-36NX" 0603 3173.64,235.33 r90 top value=10mH
MAX-M8Q "MAX-M8Q" "MAX M8Q" 2816.39,117.47 r180 bottom locked
NT1 "Net-Tie" Net-Tie_50milWide_30milLong 587.81,815.94 r180 top net-tie
NT2 "Net-Tie" Net-Tie_50milWide_30milLong 517.67,860.72 r90 top net-tie
NT3 "Net-Tie" Net-Tie_50milWide_30milLong 518.7,764.27 r270 top net-tie
NT4 "Net-Tie" Net-Tie_50milWide_30milLong 448.73,813.74 r180 top net-tie
P1 "TSW-102-07-G-S" SIP2 2433.39,829.25 r270 top
P11 "Header 4" HDR1X4 2835.92,1215.36 r90 bottom
PDB1 "Header 8" HDR1X8 3396.36,928.28 r90 top locked
PL1 "0" SIP2 3339.05,1820.83 r0 top
PSO1 "TSW-102-07-G-S" SIP2 1301.45,434.76 r270 top
Q1 "BSS123" SOT-23 2287.97,381.09 r180 top value=100V
R1 "1K" 0603 587.52,1684.69 r270 top
R3 "ERJ-2GE0R00X" 0603 1047.45,956.76 r0 bottom value=0
R4 "CRCW040210K0FKED" 0402 430.99,1688.1 r0 bottom value=10.0k
R5 "RMCF0603ZT0R00" 0603 679.46,2165.52 r270 top value=0
R7 "76.8K" 0603 2960.45,946.76 r90 top
R8 "309K" 0603 3019.45,996.76 r270 top
R8G "10mΩ" 0603 3232.49,285.06 r270 top
R11 "CRCW04020000Z0EDHP" 1206 2065.24,504.38 r0 bottom value=0
R12 "NC.309K" 0603 3077.45,804.76 r270 top
R14 "ERJ-2GE0R00X" 0603 906,976.2 r180 bottom value=0
R15 "CRCW040261R9FKED" 0603 2991.99,1401.59 r90 bottom value=61.9
R16 "ERJ-2GE0R00X" 0603 3055.59,2017.08 r180 bottom value=0
R17 "ERJ-2GE0R00X" 0603 574.32,640.6 r90 top value=0
R18 "CRCW040210K0FKED" 0603 2928.04,1443.73 r90 bottom value=10.0k
R21 "ERJ-2GE0R00X" 0603 2912.77,2075.32 r270 bottom value=0
R22 "ERJ-2GE0R00X" 0603 1291.45,551.76 r90 top value=0
R23 "ERJ-2GE0R00X" 0603 1434.1,554.42 r90 top value=0
R24 "CRCW040261R9FKED" 0603 3052.99,1451.59 r270 bottom value=61.9
R25 "ERJ-2GE0R00X" 0603 3123.36,2076.08 r270 bottom value=0
R30 "CSNL1206FT1L00" 1206L 129.45,472.67 r180 bottom value=0.001
R31 "ERJ-2GE0R00X" 0603 1078.46,842.9 r90 bottom value=0
R34 "CRCW04022K20JNED" 0402 463.71,1688.1 r0 bottom value=2.2k
R37 "ERJ-2GE0R00X" 0603 400.98,1520.33 r180 top value=0
R40 "CRCW040210K0FKED" 0603 172,1961 r90 top value=10.0k
R43 "CRCW040247K5FKED" 0603 230,1931 r90 top value=47.5k
R44 "CRCW040210K0FKED" 0603 115,1933.05 r90 top value=10.0k
R45 "CRCW040210K0FKED" 0603 291.96,1333.84 r0 top value=10.0k
R46 "ERJ-1GNF33R2C" 0603 191.37,1862.99 r270 top value=33.2
R47 "ERJ-1GNF33R2C" 0603 150,1383 r270 top value=33.2
R48 "ERJ-1GNF33R2C" 0603 114.8,1862.8 r270 top value=33.2
R49 "ERJ-1GNF33R2C" 0603 210.44,1382.77 r270 top value=33.2
R50 "ERJ-2GE0R00X" 0402 480.74,2208 r0 bottom value=0
R51 "ERJ-2GE0R00X" 0402 446.46,2208 r0 bottom value=0
R52 "CRCW04023K30JNED" 0603 3175.02,1443.57 r90 bottom value=3.3k
R53 "CRCW04024K70JNED" 0603 3298.11,2076.08 r270 bottom value=4.7k
R54 "ERJ-2GE0R00X" 0603 3238.92,2076.08 r270 bottom value=0
R55 "CRCW040233K0JNED" 0603 3233.95,1492.41 r270 bottom value=33k
R56 "31K" 0805 2626.45,862.76 r180 top
R57 "10K" 0805 2803.04,962.05 r180 top
R58 "200K" 0805 2896.93,946.76 r0 bottom
R61 "ERJ-1GNF33R2C" 0603 83.61,1382.19 r270 top value=33.2
R63 "ERJ-2GE0R00X" 0603 721.37,915.88 r0 bottom value=0
R71 "ERJ-2GE0R00X" 0603 228.67,965.87 r90 top value=0
R73 "HCJ0603ZT0R00" FP-HCJ0603ZT0R00_0603-MFG 174.55,1083.16 r180 bottom value=0
R74 "ERJ-1GNF33R2C" 0402 852.83,1695.43 r0 bottom value=33.2
R75 "ERJ-2GE0R00X" 0402 391.23,914.77 r270 bottom value=0
R76 "ERJ-2GE0R00X" 0603 274.09,724.53 r0 bottom value=0
R79 "NC 2.49K" 0603 530.92,1634.53 r90 top value=2.49k
R89 "NC 2.49K" 0603 397.14,2144.99 r90 bottom value=2.49k
R96 "ERJ-1GNF33R2C" 0402 681.93,1705.35 r0 bottom value=33.2
R99 "CRCW04021K00FKED" 0603 795.58,726.29 r180 top value=1.00k
R100 "ERJ-1GNF33R2C" 0402 714.93,1705.35 r0 bottom value=33.2
R102 "NC.10K" 0603 746.64,785.1 r0 top value=10.0k
R103 "CRCW04021K00FKED" 0603 2664.49,130.98 r270 top value=1.00k
R104 "HCJ0603ZT0R00" 1206 810.37,1119.84 r90 bottom value=0
R106 "CRCW040210K0FKED" 0603 744.35,666.13 r0 top value=10.0k
R110 "CRCW040210R0JNED" 0603 3394.68,2140.28 r270 bottom value=10
R111 "HCJ0603ZT0R00" FP-HCJ0603ZT0R00_0603-MFG 174.55,1007.86 r180 bottom value=0
R116 "CRCW04020000Z0EDHP" 1206 834.45,689.94 r0 bottom value=0
R125 "CRCW040210K0FKED" 0603 325.92,666.39 r180 bottom value=10.0k
R133 "CRCW04021K00FKED" 0603 1245.07,1528.27 r90 bottom value=1.00k
R156 "CRCW04026K04FKED" 0603 1256.95,1364.67 r270 bottom value=6.04k
R159 "CRCW04021K00FKED" 0603 2350.32,653.05 r270 bottom value=1.00k
R172 "CRCW040210K5FKED" 0603 1133.42,1432.58 r0 bottom value=10.5k
R178 "ERJ-1GNF33R2C" 0402 748.93,1704.72 r0 bottom value=33.2
R186 "ERJ-2GE0R00X" 0603 763.22,764.75 r0 bottom value=0
R190 "ERJ-2GE0R00X" 0603 938.45,811.76 r180 top value=0
R193 "CRCW040233R2FKED" 0603 685.06,841.75 r0 top value=33.2
R200 "HCJ0603ZT0R00" FP-HCJ0603ZT0R00_0603-MFG 546.5,170.76 r180 bottom value=0
R210 "NC.10K" 0603 506.71,690.6 r270 top value=10.0k
R218 "CRCW02010000Z0ED" 0603 1363.82,603.71 r270 top value=0
R225 "ERJ-1GNF33R2C" 0402 781.93,1704.72 r0 bottom value=33.2
R230 "ERJ-1GNF33R2C" 0402 817.28,1684.08 r0 bottom value=33.2
R233 "ERJ-2GE0R00X" 0603 3292.55,1620.91 r270 bottom value=0
R234 "ERJ-1GNF33R2C" 0402 874.72,1757.69 r90 bottom value=33.2
R237 "ERJ-1GNF33R2C" 0402 905.2,1790.66 r90 bottom value=33.2
R238 "ERJ-1GNF33R2C" 0402 912.71,1825.22 r90 bottom value=33.2
R239 "ERJ-1GNF33R2C" 0402 905.71,1860.22 r90 bottom value=33.2
R240 "ERJ-1GNF33R2C" 0402 894.69,1893.38 r90 bottom value=33.2
R242 "ERJ-2GEJ101X" 0402 440.74,1905.35 r90 bottom value=100
R245 "ERJ-1GNF33R2C" 0402 793.48,2142.27 r90 bottom value=33.2
R246 "ERJ-2GE0R00X" 0402 549.94,1869.94 r270 bottom value=0
R247 "ERJ-1GNF33R2C" 0402 596.19,1708.33 r0 bottom value=33.2
R248 "CRCW06031M00FKEA" 0603 472.64,1921.91 r270 top value=1.00Meg
R249 "ERJ-1GNF33R2C" 0402 524.79,1775.15 r0 bottom value=33.2
R251 "NC 2.49K" 0402 556.77,2098.85 r180 bottom value=2.49k
R253 "CRCW04022K49FKED" 0603 862.96,2185.42 r0 bottom value=2.49k
R254 "CRCW04022K49FKED" 0603 862.96,2089.55 r0 bottom value=2.49k
R255 "NC 2.49K" 0603 994.45,2050.76 r90 top value=2.49k
R256 "CRCW04022K49FKED" 0603 920.95,2050.07 r90 top value=2.49k
R257 "CRCW04022K49FKED" 0603 860.25,2050.07 r90 top value=2.49k
R262 "ERJ-2GEJ511X" 0603 97.34,695.6 r0 top value=510
R263 "ERJ-2GEJ511X" 0603 2027.33,367.8 r90 top value=510
R264 "CRCW040210K0FKED" 0603 938.25,573.99 r180 top value=10.0k
R265 "CRCW04020000Z0EDHP" 0603 501.42,2331.03 r0 bottom value=0
R266 "ERJ-2GEJ511X" 0603 2230.96,445.59 r0 top value=510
